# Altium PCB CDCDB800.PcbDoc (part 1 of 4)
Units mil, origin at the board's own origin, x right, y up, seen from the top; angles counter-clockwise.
Board outline 4100 x 4100 mil, 4 copper layers (Layer 1 - Top Layer, Layer 2 - GND, Layer 3 - PWR, Layer 4 - Bottom Layer), stack 61.2 mil thick; 245 components, 143 nets, 740 pads, 720 vias.
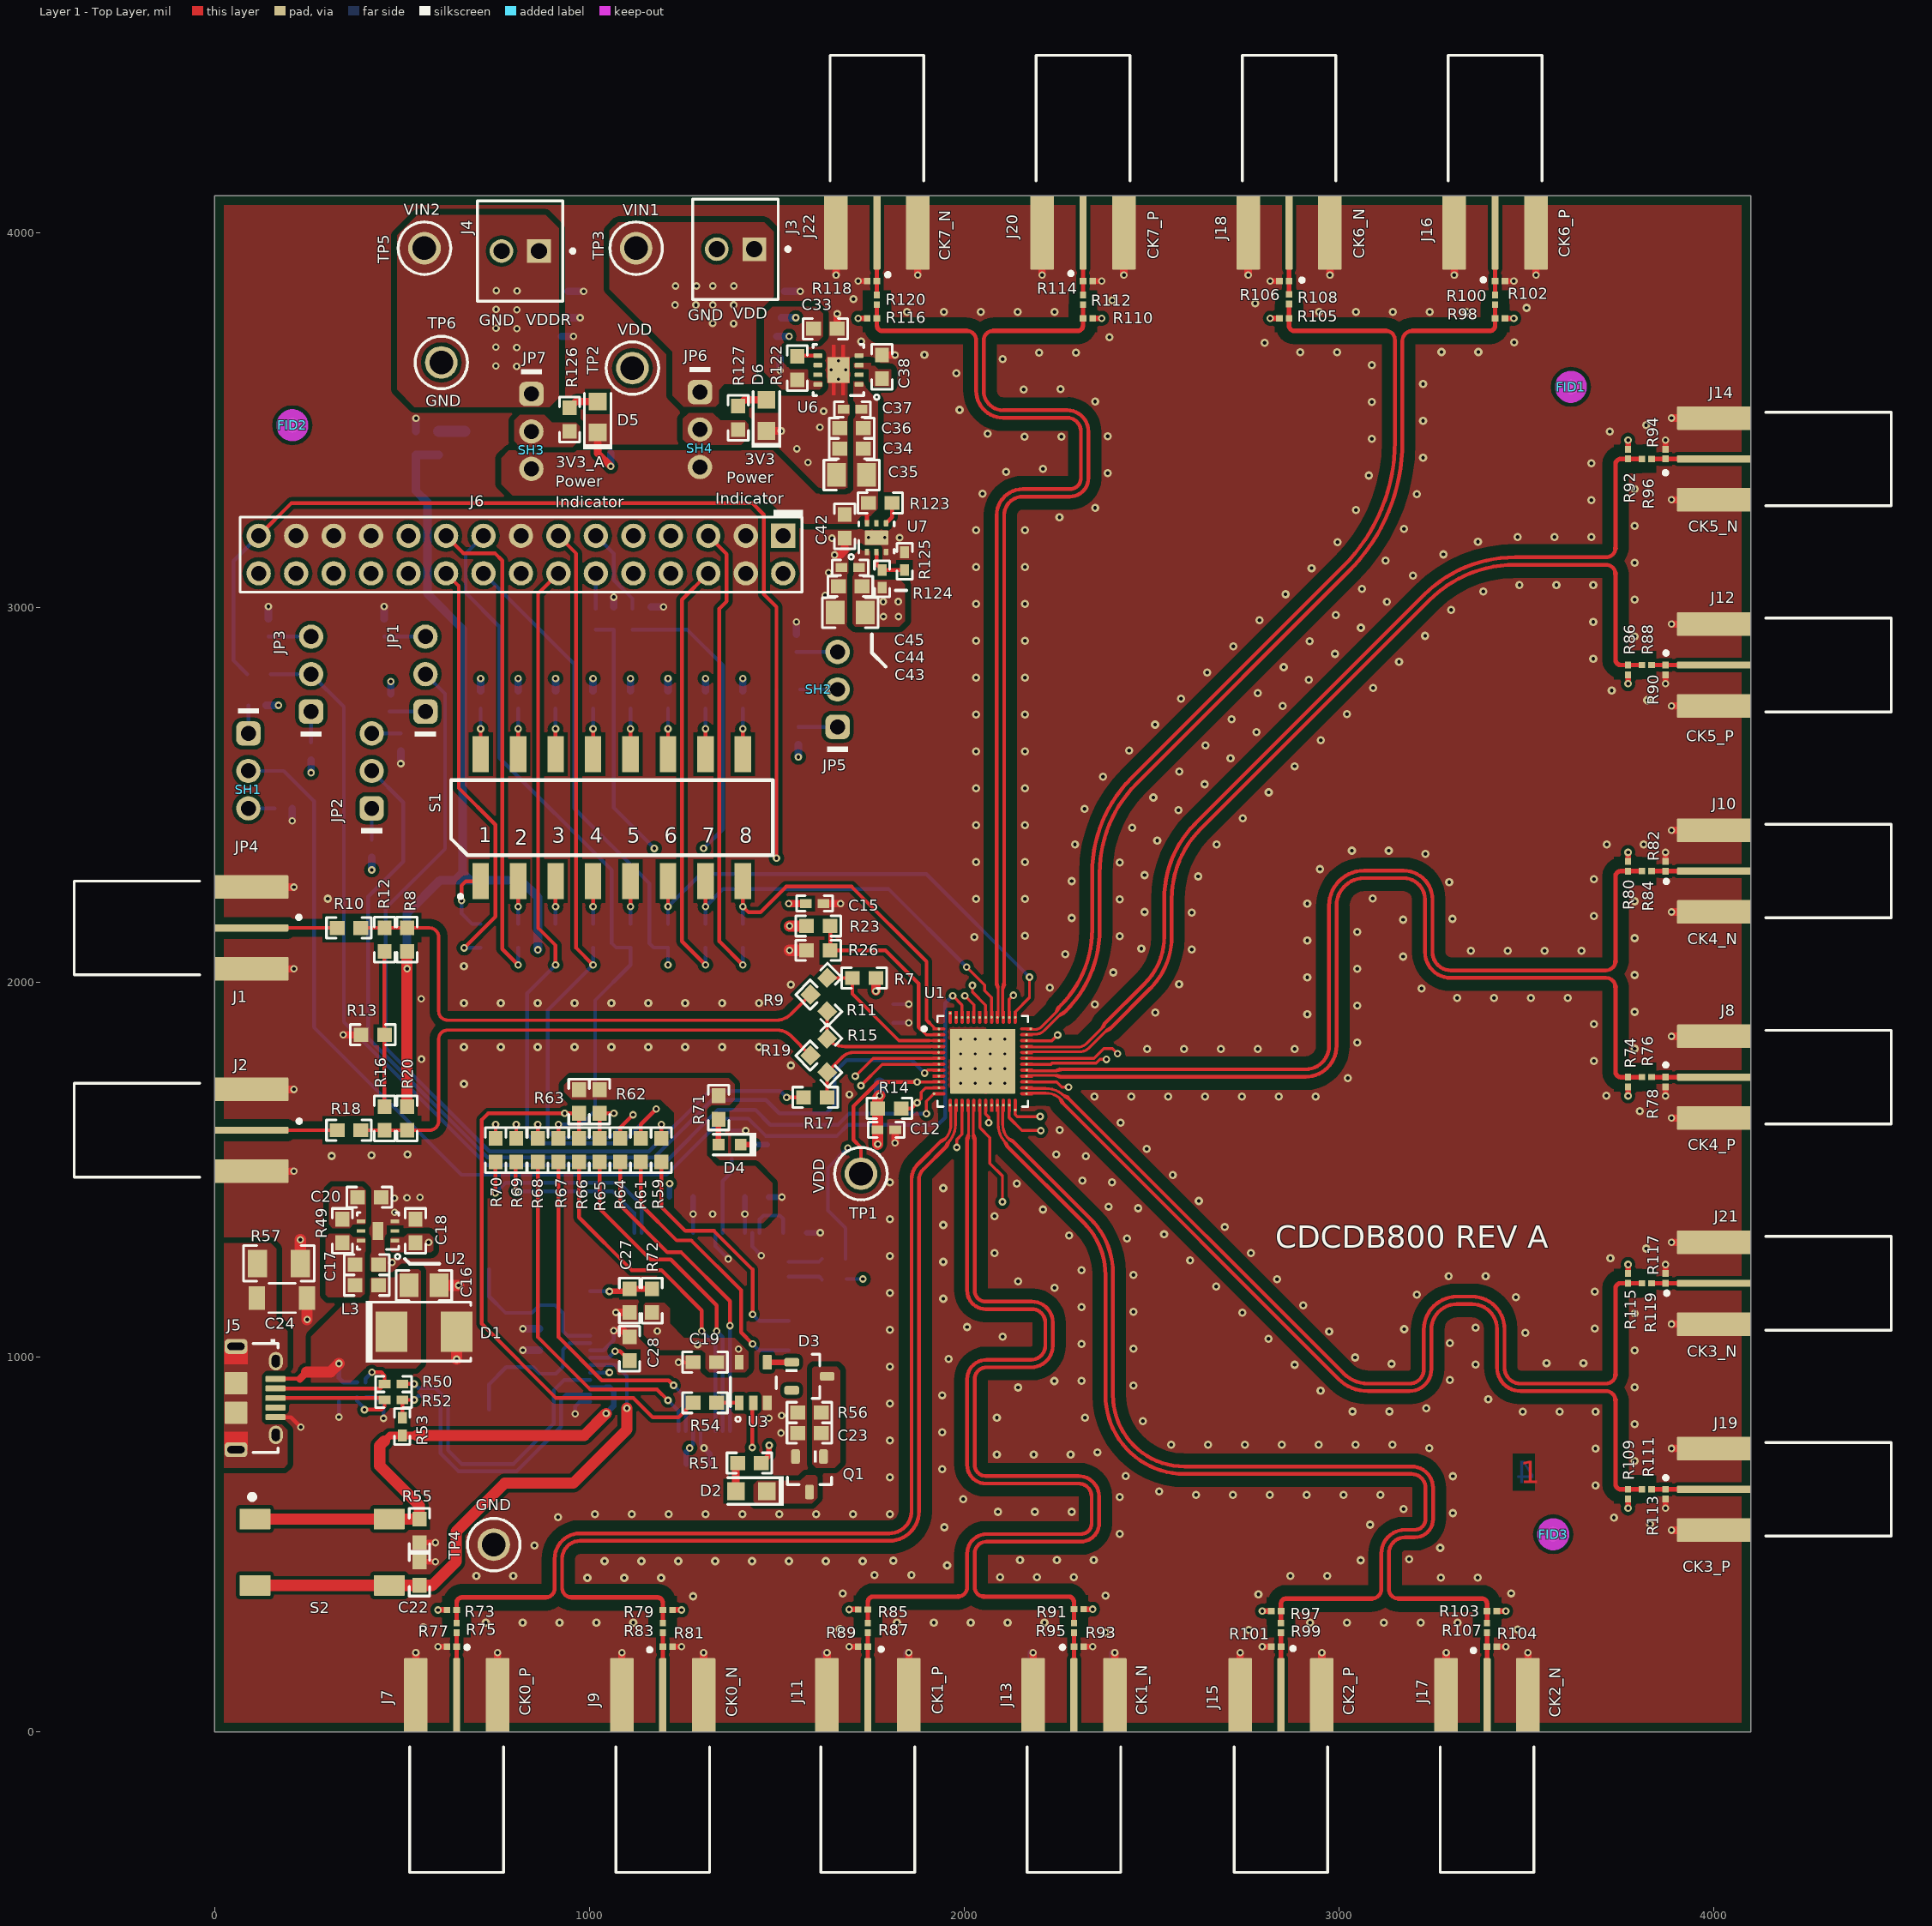
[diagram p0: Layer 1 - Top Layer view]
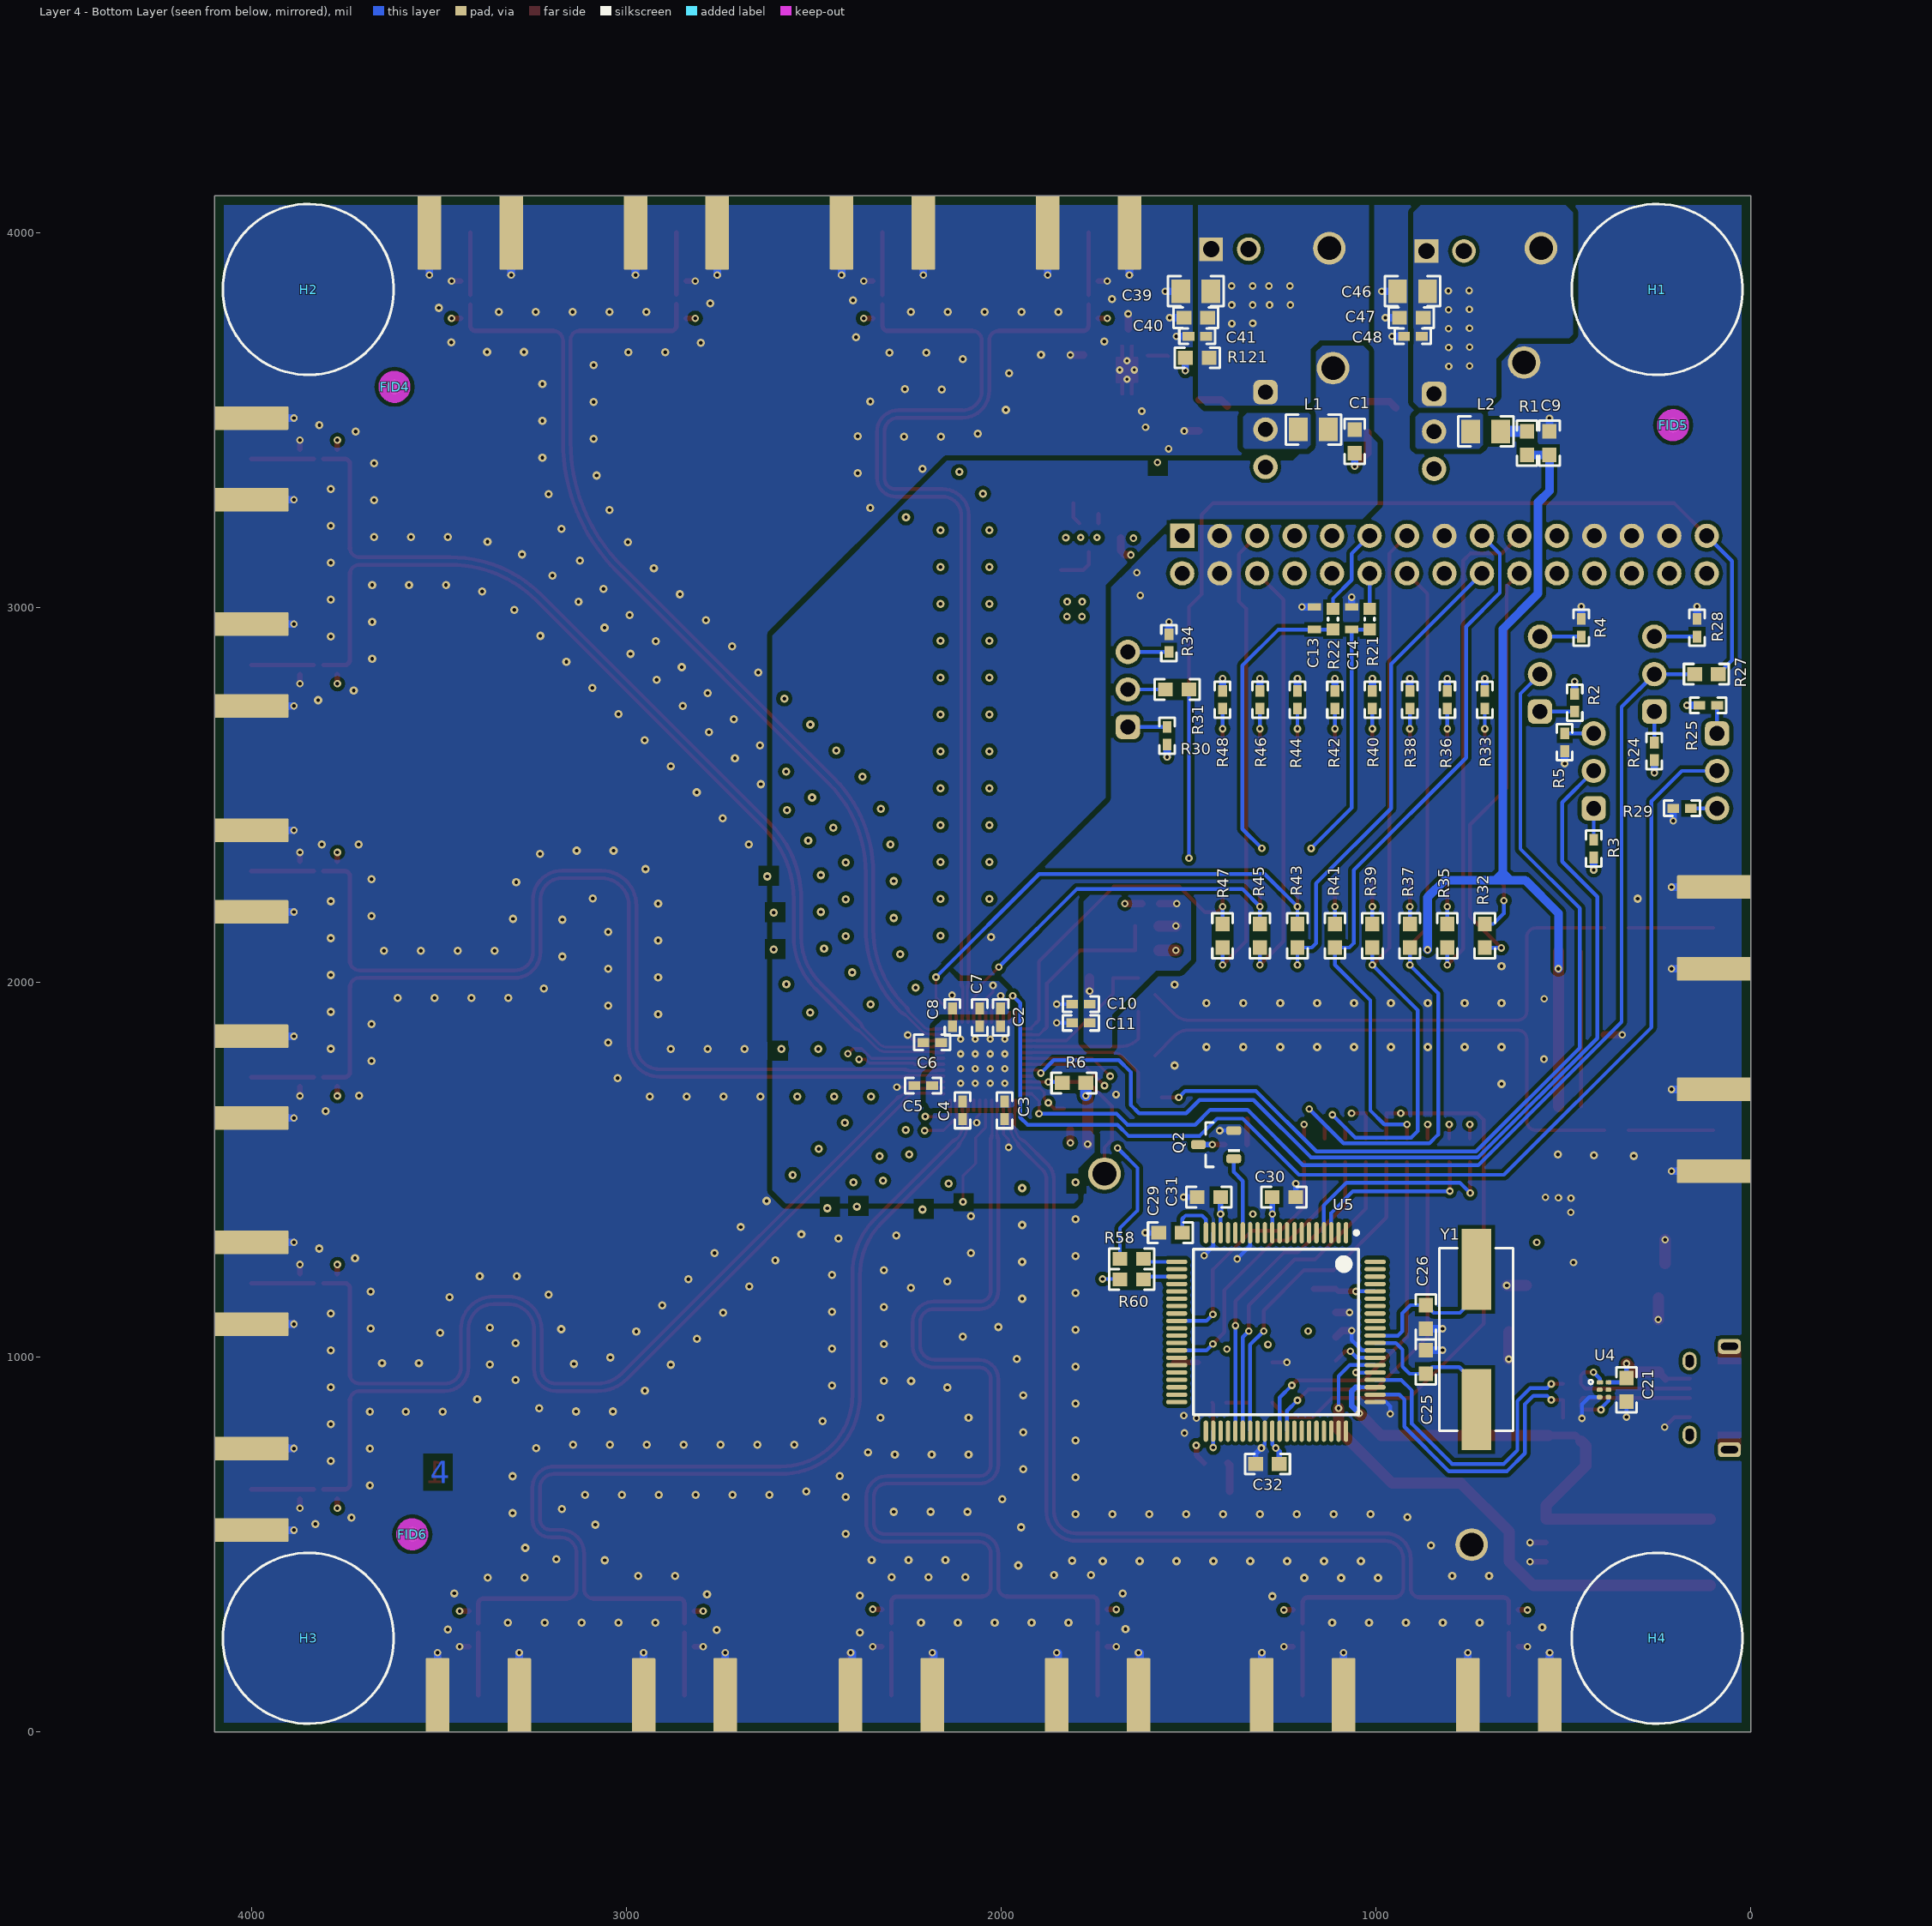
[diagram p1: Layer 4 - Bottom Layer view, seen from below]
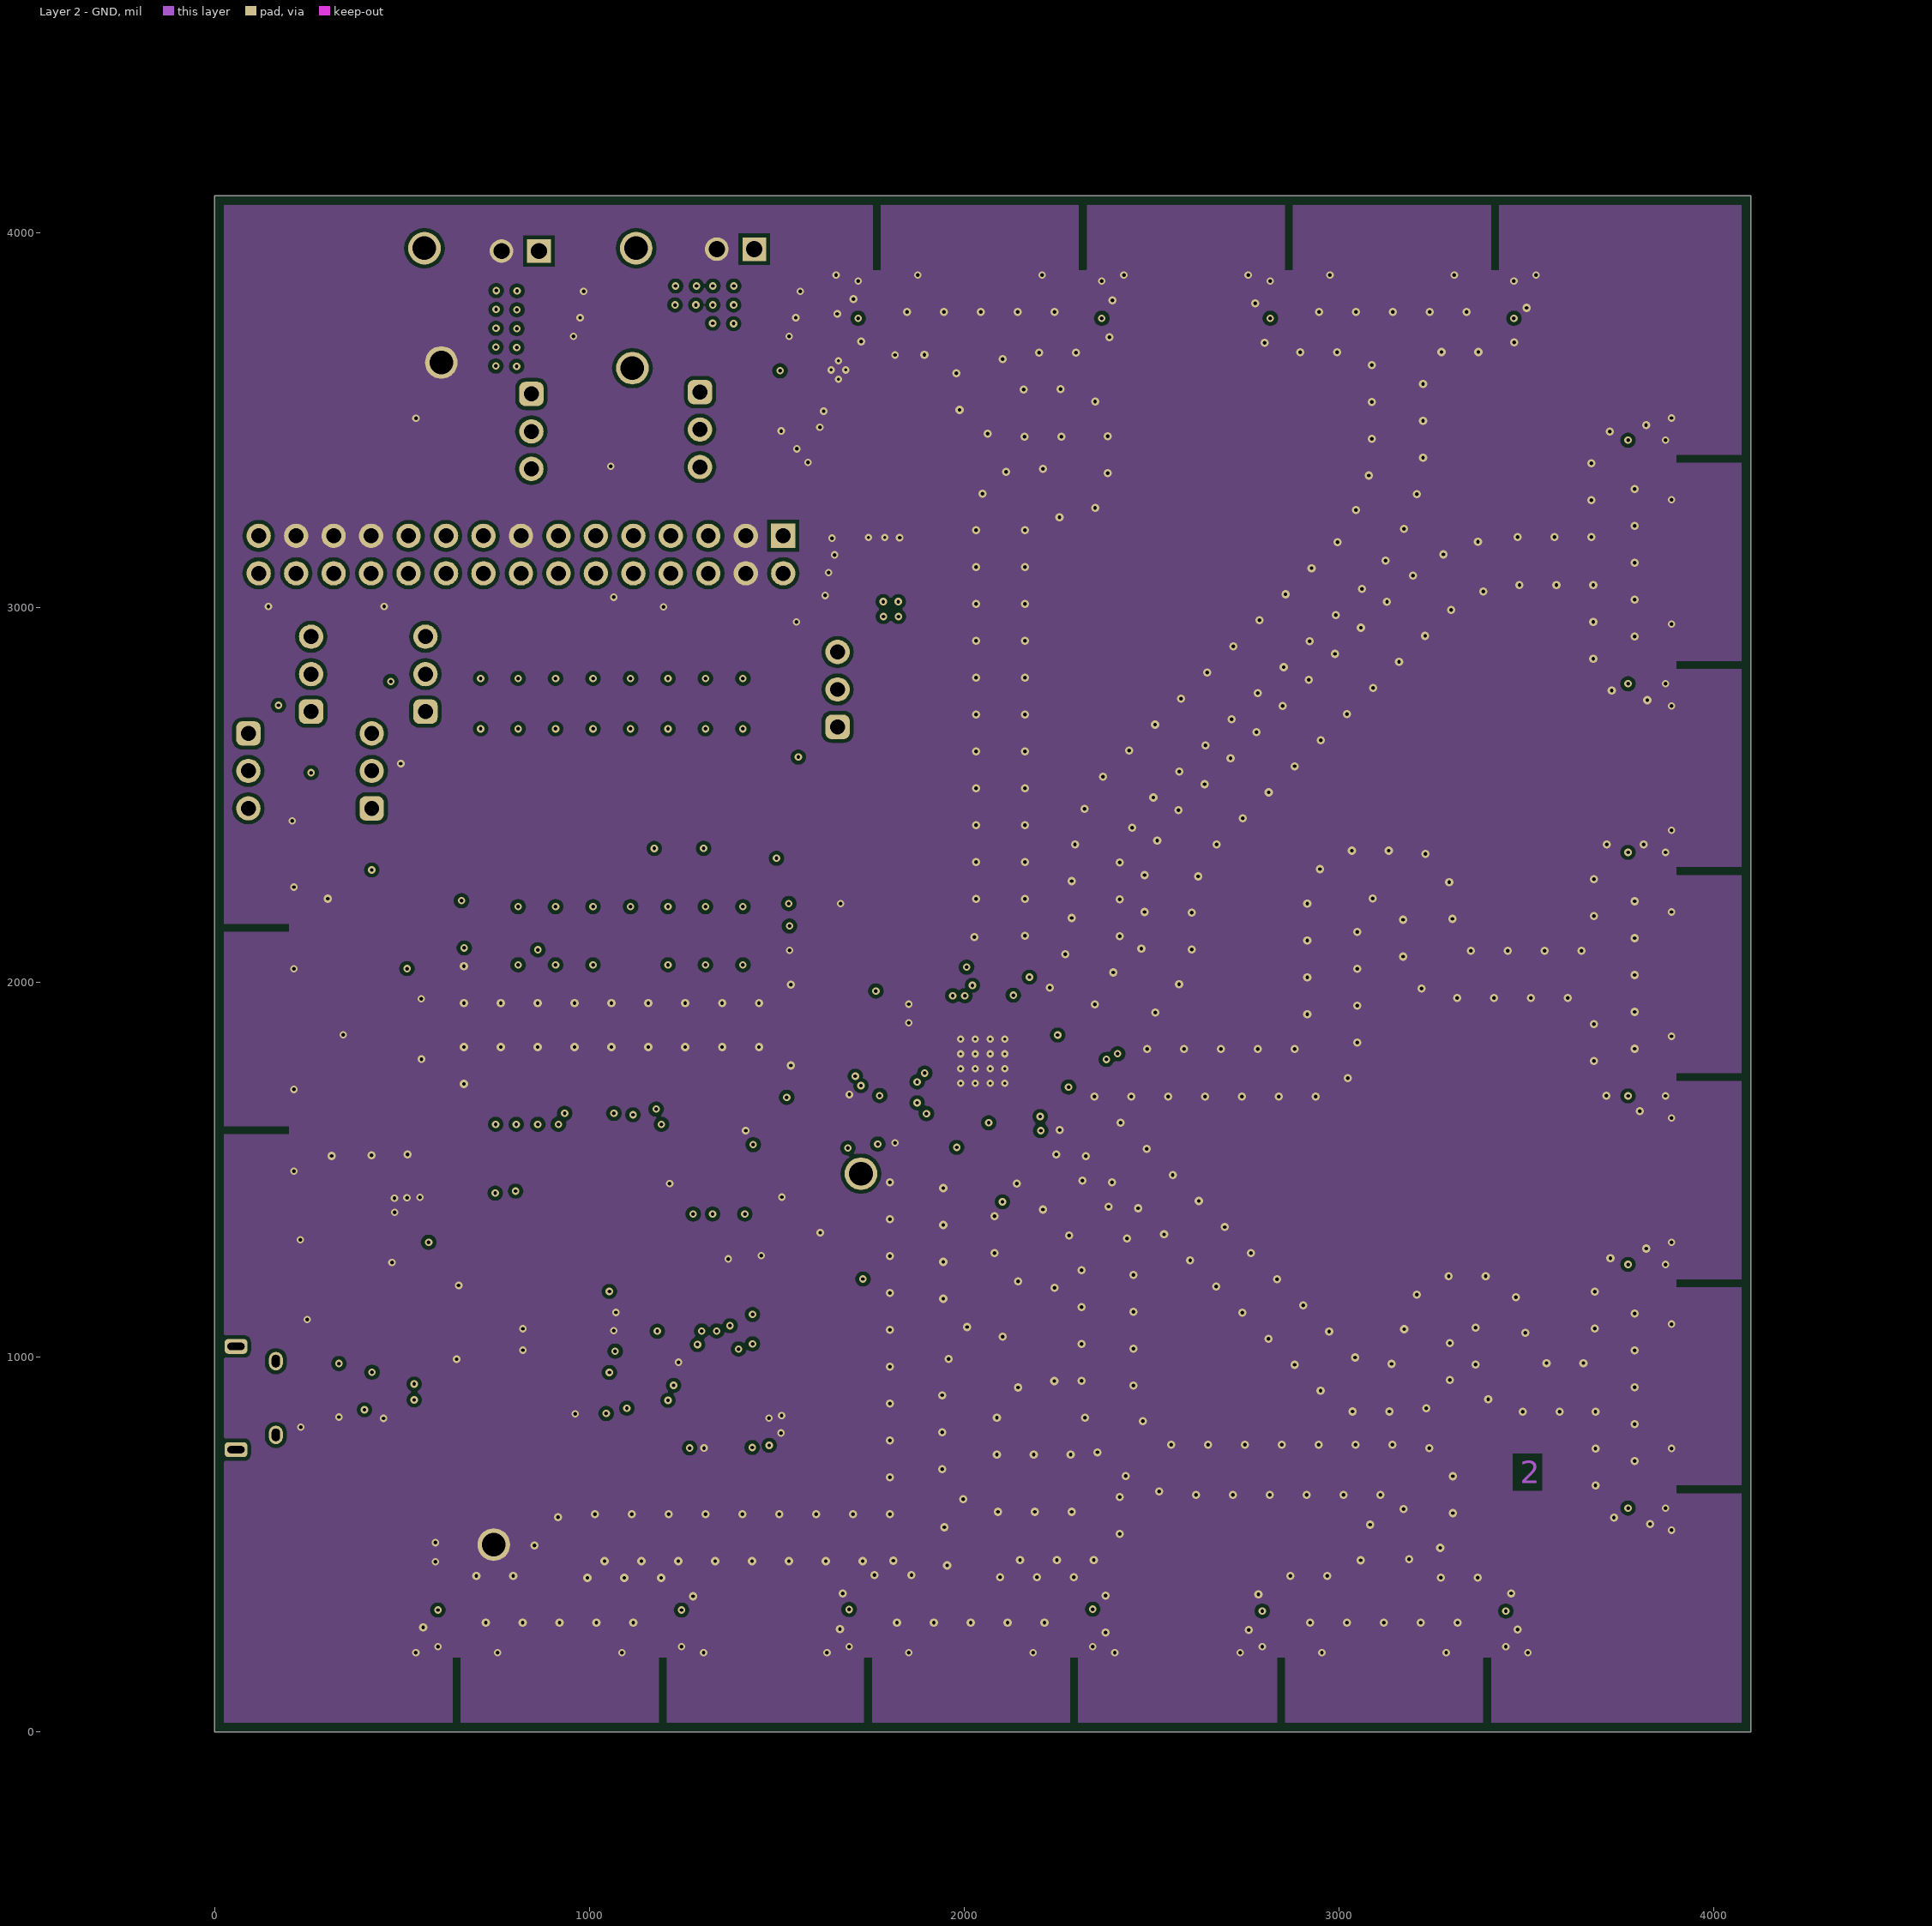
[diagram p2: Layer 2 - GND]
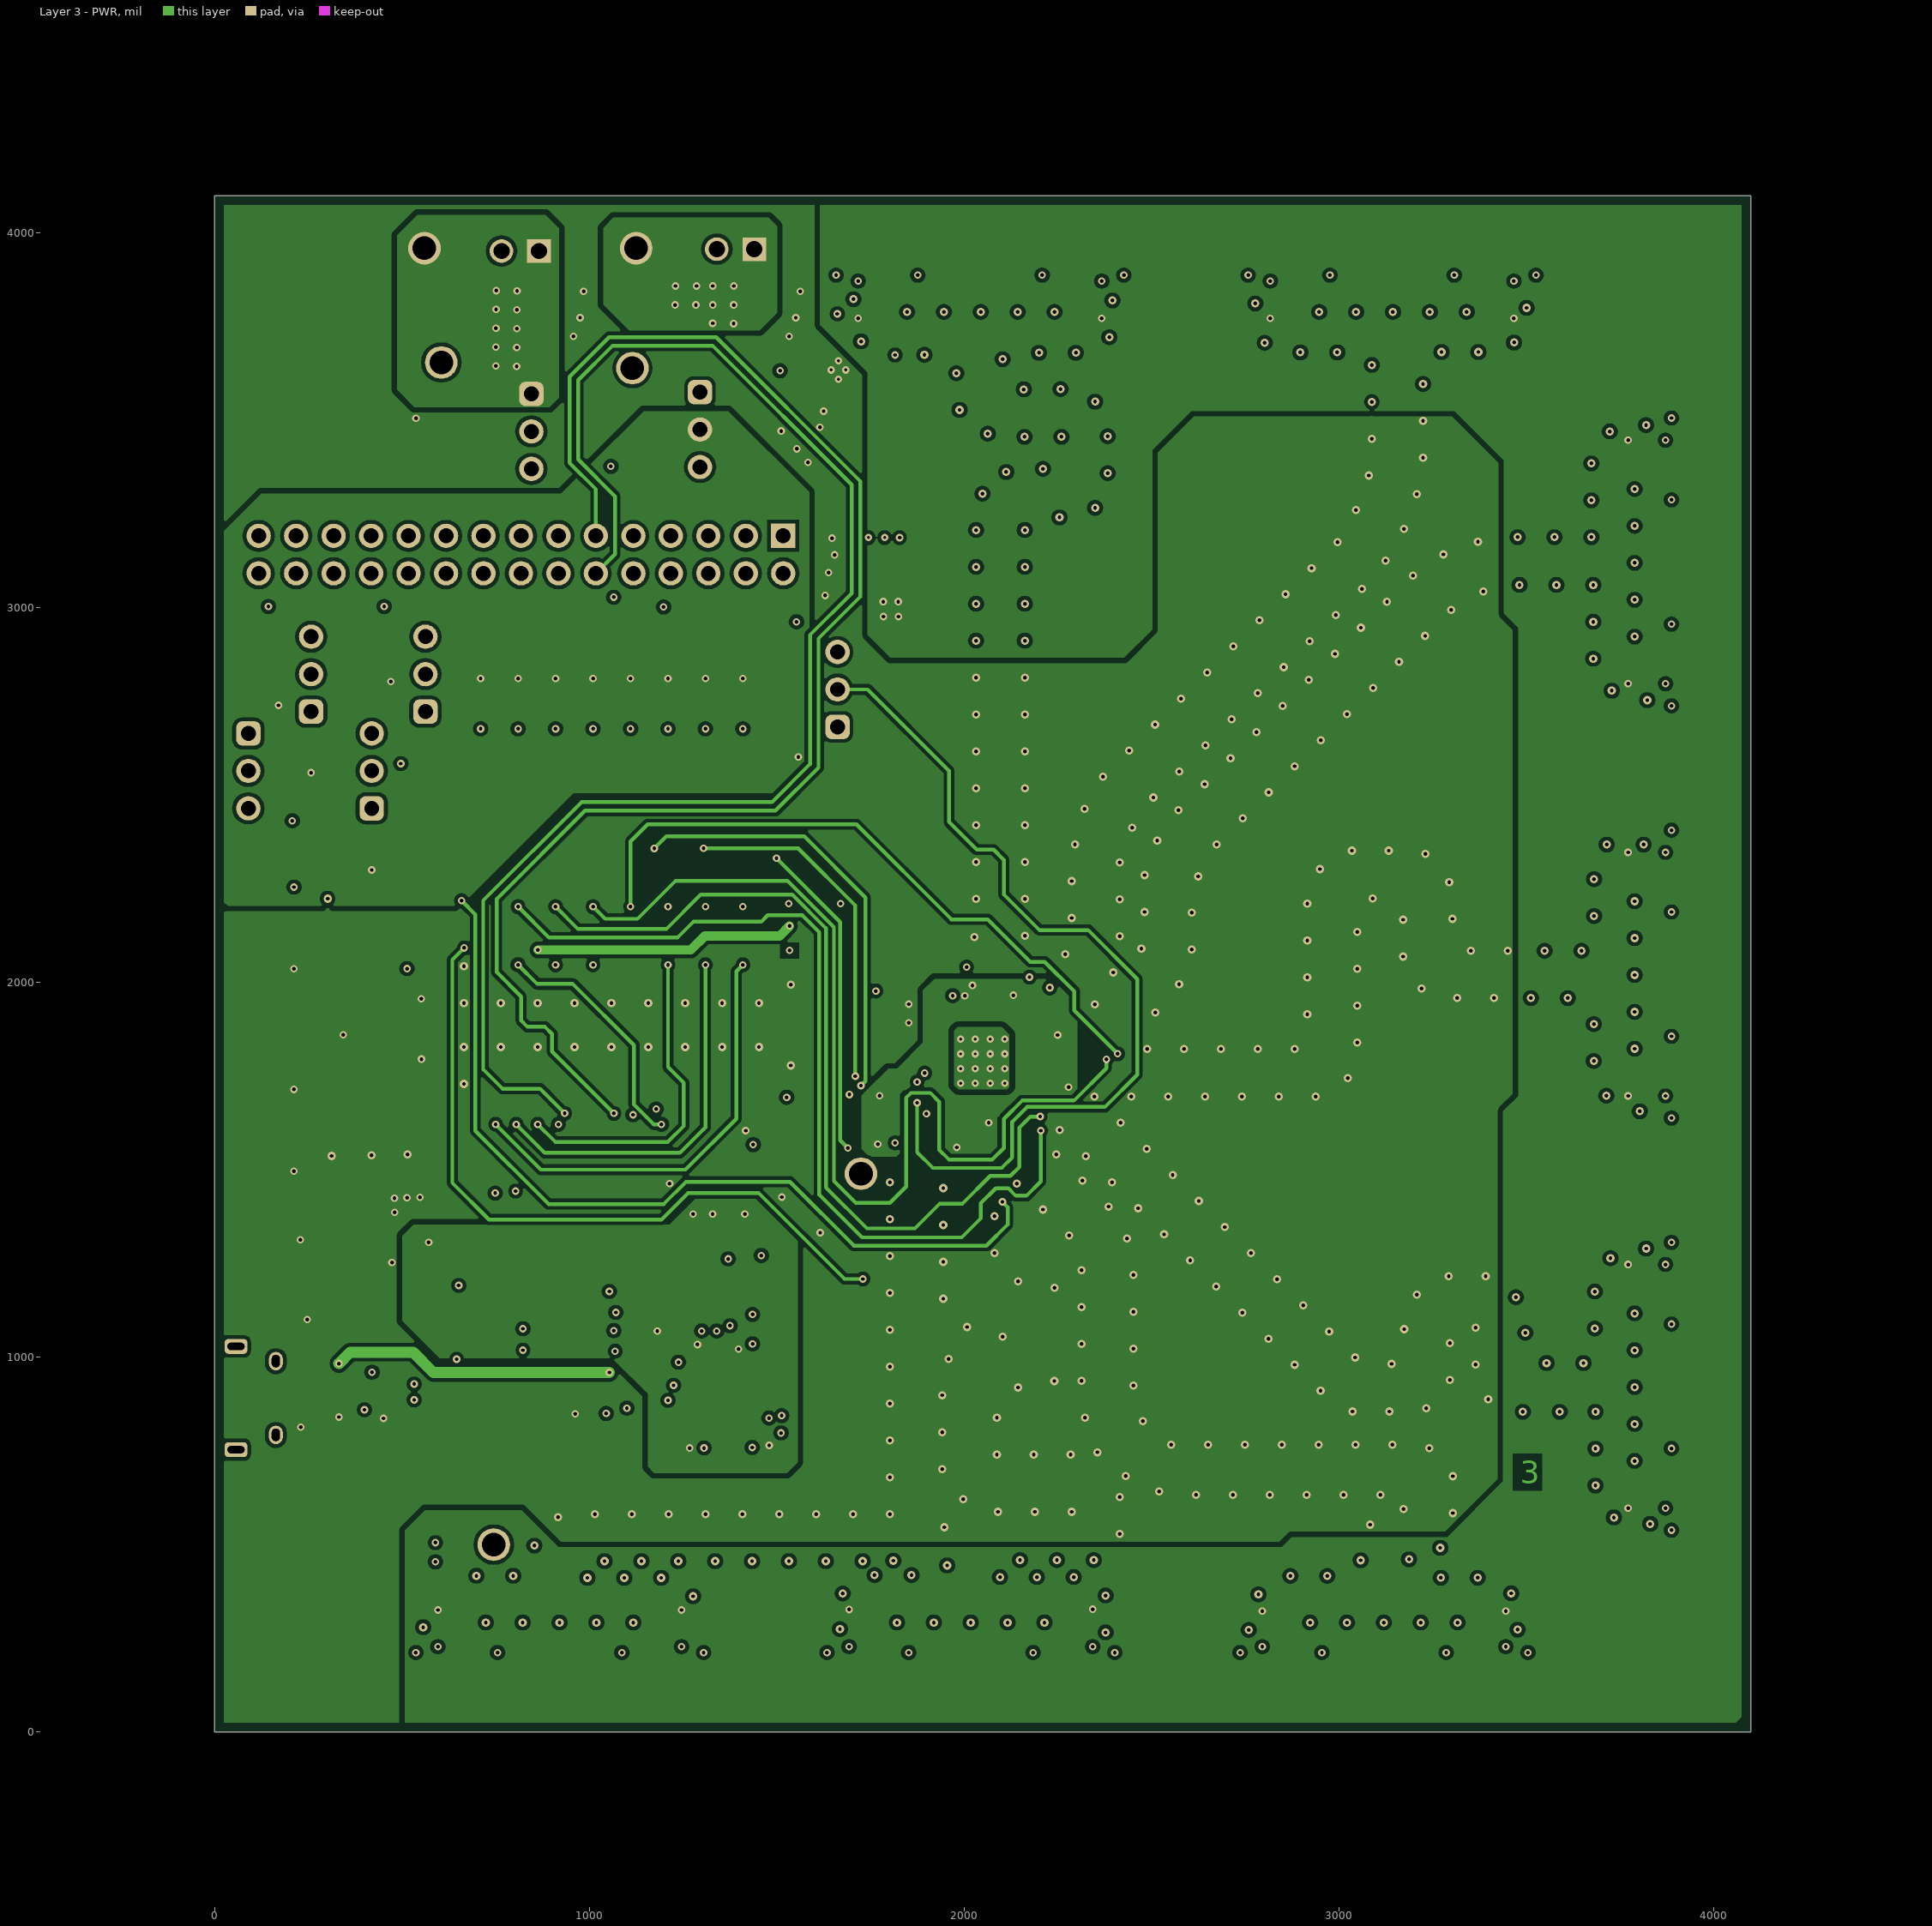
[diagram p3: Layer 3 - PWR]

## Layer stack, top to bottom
Top Solder: solder mask 0.4, Solder Resist, Dk 3.5
Layer 1 - Top Layer: signal copper 2.1
Dielectric 1: prepreg 5.5, FR-4 High Tg, Dk 4.2
Layer 2 - GND: signal copper 1.4
Dielectric 2: core 43.2, FR-4 High Tg, Dk 4.2
Layer 3 - PWR: signal copper 1.4
Dielectric 3: prepreg 5.5, FR-4 High Tg, Dk 4.2
Layer 4 - Bottom Layer: signal copper 2.1
Bottom Solder: solder mask 0.4, Solder Resist, Dk 3.5

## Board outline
0,0 4100,0 4100,4100 0,4100

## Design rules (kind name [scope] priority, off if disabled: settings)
AcuteAngle [All] p1: minimum=4.50000000000000E+0001 checktracksonly=FALSE
AssemblyTestPointUsage [All] p1: valid=2
BoardOutlineClearance BoardOutlineClearance_MountingHoles [OnCopper and InComponentClass('Mounting Holes')] p1: gap=40 ignorepadtopadclearanceinfootprint=FALSE
BoardOutlineClearance BoardOutlineClearance_Poly [OnCopper and IsPoly] p2: gap=25 ignorepadtopadclearanceinfootprint=FALSE
BoardOutlineClearance [OnCopper and Not InComponentClass('Logo') and not InComponentClass('FiducialMark') and not InRegion(1000,500,4000,800) and not InPoly] p3: gap=0 ignorepadtopadclearanceinfootprint=FALSE
Clearance Clearance_keepout [HasFootprint('Fiducial10-20') and IsPad vs HasFootprint('Fiducial10-20') and Isarc] p1: gap=0 ignorepadtopadclearanceinfootprint=FALSE
Clearance Clearance_85ohms [InPolygon vs InNetClass('85ohms')] p2: gap=30 ignorepadtopadclearanceinfootprint=FALSE
Clearance Clearance_50ohms [InPolygon vs InNetClass('50ohms')] p3: gap=20 ignorepadtopadclearanceinfootprint=FALSE
Clearance Clearance_Poly_POLY [InPolygon vs InPolygon] p4: gap=15 ignorepadtopadclearanceinfootprint=FALSE
Clearance Clearance_Poly_1 [InPolygon] p5: gap=10 ignorepadtopadclearanceinfootprint=FALSE
Clearance [All] p6: gap=5 ignorepadtopadclearanceinfootprint=FALSE
ComponentClearance ComponentClearance_1 [HasFootprint('SNT-100-BK-G')] p1: gap=0 collisioncheckmode=3 verticalgap=0 showdistances=FALSE
ComponentClearance ComponentClearance_res [InComponent('R15') vs InComponent('R19')] p2: gap=0 collisioncheckmode=3 verticalgap=0 showdistances=FALSE
ComponentClearance ComponentClearance_res_1 [InComponent('R9') vs InComponent('R11')] p3: gap=0 collisioncheckmode=3 verticalgap=0 showdistances=FALSE
ComponentClearance [All] p4: gap=10 collisioncheckmode=3 verticalgap=10 showdistances=FALSE
DiffPairsRouting [All] p1: maxlimit=17.6 minlimit=5 mostfreqgap=10 toplayer_minwidth=7.5 toplayer_maxwidth=10 toplayer_prefwidth=10 midlayer1_minwidth=7.5 midlayer1_maxwidth=10 midlayer1_prefwidth=10 midlayer2_minwidth=7.5 midlayer2_maxwidth=10 midlayer2_prefwidth=10 bottomlayer_minwidth=7.5 bottomlayer_maxwidth=10 bottomlayer_prefwidth=10 maxuncoupledlength=1000
FabricationTestPointUsage TestPointUsage [All] p1: valid=2 allowmultiple=FALSE
FabricationTestpoint Testpoint [All] p1: side=3 testpointundercomponent=TRUE minsize=40 maxsize=100 preferedsize=60 minholesize=0 maxholesize=40 preferedholesize=32 testpointgrid=1 allowsidetop=TRUE allowsidebottom=TRUE usegrid=TRUE gridtolerance=0.01
FanoutControl Fanout_LCC [IsLCC] p1: bgadir=Out bgaviamode=Centered fanoutstyle=Auto fanoutdirection=Alternating viagrid=1 // Fanout_LCC (Default Rule)
FanoutControl Fanout_BGA [IsBGA] p2: bgadir=Out bgaviamode=Centered fanoutstyle=Auto fanoutdirection=Alternating viagrid=1 // Fanout_BGA (Default Rule)
FanoutControl Fanout_Default [All] p4: bgadir=Out bgaviamode=Centered fanoutstyle=Auto fanoutdirection=Alternating viagrid=1 // Fanout_Default (Default Rule)
FanoutControl Fanout_Small [(CompPinCount < 5)] p5: bgadir=Out bgaviamode=Centered fanoutstyle=Auto fanoutdirection=OutThenIn viagrid=1 // Fanout_Small (Default Rule)
HoleSize [All] p1: absolutevalues=TRUE maxlimit=251 minlimit=6 maxpercent=80.000 minpercent=20.000
MinimumAnnularRing MinimumAnnularRing_ThermalPadVias [IsVia and InAnyComponent] p1: minimumring=5.91
MinimumAnnularRing [All] p2: minimumring=3
MinimumSolderMaskSliver MinimumSolderMaskSliver_Logo [InComponentClass('Logo') vs InComponentClass('Logo')] p1: minsoldermaskwidth=0.7
MinimumSolderMaskSliver [All] p2: minsoldermaskwidth=3
PlaneConnect [All] p1: planeconnectstyle=Relief reliefexpansion=10 reliefentries=4 reliefconductorwidth=10 reliefairgap=10
PolygonConnect PolygonConnect_1 [InNet('USB_GND') vs (InComponent('R46') OR InComponent('C19'))] p1: connectstyle=Relief reliefconductorwidth=10 reliefentries=4 polygonreliefangle="90 Angle" airgapwidth=10
PolygonConnect [All] p2: connectstyle=Direct reliefconductorwidth=10 reliefentries=4 polygonreliefangle="90 Angle" airgapwidth=10
RoutingVias ThermalPadVias [IsVia and InAnyComponent] p1: holewidth=7.87 width=19.68 viastyle="Through Hole" minholewidth=7.87 minwidth=19.68 maxholewidth=12.99 maxwidth=23.62
RoutingVias [All] p2: holewidth=16 width=34 viastyle="Through Hole" minholewidth=6 minwidth=12 maxholewidth=40 maxwidth=65
SilkToBoardRegionClearance [Not ((IsComment or IsDesignator) And (Hide <> 'False')) and not InRegion(1000,500,4000,800)] p1:
SilkToSilkClearance SilkToSilkClearance_Pb-FreeLogo [(HasFootprint('Pb-Free_Overlay_Medium') OR HasFootprint('Pb-Free_Overlay_Small')) vs (HasFootprint('Pb-Free_Overlay_Medium') OR HasFootprint('Pb-Free_Overlay_Small'))] p1: silktosilkclearance=0
SilkToSilkClearance [All] p2: silktosilkclearance=4
SilkToSolderMaskClearance SilkToComponentPadClearance [(IsPad or IsFill or IsRegion) and InAnycomponent] p1: minsilkscreentomaskgap=0 clearancetoexposedcopper=TRUE
SilkToSolderMaskClearance "Silk to Solder Mask Opening" [All] p2: minsilkscreentomaskgap=0 clearancetoexposedcopper=FALSE
SolderMaskExpansion SolderMaskExpansion_NPTH [IsThruPin and (PadIsPlated = 'FALSE')] p1: expansion=5 soldermaskfromhole=TRUE
SolderMaskExpansion SolderMaskExpansion_PTH [IsThruPin] p2: expansion=2.5
SolderMaskExpansion [All] p3: expansion=0
Width [All] p1: maxlimit=100 minlimit=5 preferedwidth=10 checkconnectedcopper=TRUE
15 further rules are at their usual default settings.

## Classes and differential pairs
component class Shunt: SH1 SH2 SH3 SH4
net class 50ohms: CLKIN_N CLKIN_N1 CLKIN_N2 CLKIN_P CLKIN_SMA_N CLKIN_SMA_P
net class 85ohms: CK0_N CK0_P CK1_N CK1_P CK2_N CK2_P CK3_N CK3_P CK4_N CK4_P CK5_N CK5_P CK6_N CK6_P CK7_N CK7_P
component class HSDC109_Power: C33 C34 C35 C36 C37 C38 C39 C40 C41 C42 C43 C44 C45 C46 C47 C48 D5 D6 J3 J4 JP6 JP7 R121 R122 R123 R124 R125 R126 R127 TP3 TP4 TP5 TP6 U6 U7
component class HSDC109_Output: J7 J8 J9 J10 J11 J12 J13 J14 J15 J16 J17 J18 J19 J20 J21 J22 R73 R74 R75 R76 R77 R78 R79 R80 R81 R82 R83 R84 R85 R86 R87 R88 R89 R90 R91 R92 R93 R94 R95 R96 R97 R98 R99 R100 R101 R102 R103 R104 R105 R106 R107 R108 R109 R110 R111 R112 R113 R114 R115 R116 R117 R118 R119 R120
component class HSDC109_Main: C1 C2 C3 C4 C5 C6 C7 C8 C9 C10 C11 C12 C13 C14 C15 J1 J2 JP1 JP2 JP3 JP4 JP5 JP12 L1 L2 R1 R2 R3 R4 R5 R6 R7 R8 R9 R10 R11 R12 R13 R14 R15 R16 R17 R18 R19 R20 R21 R22 R23 R24 R25 R26 R27 R28 R29 R30 R31 R32 R33 R34 R35 R36 R37 R38 R39 R40 R41 R42 R43 R44 R45 R46 R47 R48 S1 TP1 TP2 U1
component class Header: J6 JP1 JP2 JP3 JP4 JP5 JP6 JP7 JP12
component class HSDC109_Hardware: !PCB FID1 FID2 FID3 FID4 FID5 FID6 H1 H2 H3 H4 SH1 SH2 SH3 SH4
component class HSDC109_Control: C16 C17 C18 C19 C20 C21 C22 C23 C24 C25 C26 C27 C28 C29 C30 C31 C32 D1 D2 D3 D4 J5 J6 L3 Q1 Q2 R49 R50 R51 R52 R53 R54 R55 R56 R57 R58 R59 R60 R61 R62 R63 R64 R65 R66 R67 R68 R69 R70 R71 R72 S2 U2 U3 U4 U5 Y1
component class FiducialMark: FID1 FID2 FID3 FID4 FID5 FID6
differential pair USB_D: +USB_D_P -USB_D_N
differential pair D: +D_P -D_N
differential pair CLKIN: +CLKIN_P -CLKIN_N
differential pair CK7: +CK7_P -CK7_N
differential pair CK7_SMA: +CK7_SMA_P -CK7_SMA_N
differential pair CK6: +CK6_P -CK6_N
differential pair CK6_SMA: +CK6_SMA_P -CK6_SMA_N
differential pair CK5: +CK5_P -CK5_N
differential pair CK5_SMA: +CK5_SMA_P -CK5_SMA_N
differential pair CK4: +CK4_P -CK4_N
differential pair CK4_SMA: +CK4_SMA_P -CK4_SMA_N
differential pair CK3: +CK3_P -CK3_N
differential pair CK3_SMA: +CK3_SMA_P -CK3_SMA_N
differential pair CK2: +CK2_P -CK2_N
differential pair CK2_SMA: +CK2_SMA_P -CK2_SMA_N
differential pair CK1: +CK1_P -CK1_N
differential pair CK1_SMA: +CK1_SMA_P -CK1_SMA_N
differential pair CK0: +CK0_P -CK0_N
differential pair CK0_SMA: +CK0_SMA_P -CK0_SMA_N
differential pair CLKIN_SMA: +CLKIN_SMA_P -CLKIN_SMA_N

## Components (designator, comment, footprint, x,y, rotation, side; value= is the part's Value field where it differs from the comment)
C1 "GRM188C81C106MA73D" 0603 1057.4,3444.52 r270 bottom value=10uF
C2 "GRM155R71A104KA01D" 0402 2002.2,1907.13 r270 bottom value=0.1uF
C3 "GRM155R71A104KA01D" 0402 1991.7,1659.2 r90 bottom value=0.1uF
C4 "GRM155R71A104KA01D" 0402 2103.7,1659.2 r90 bottom value=0.1uF
C5 "GRM155R71A104KA01D" 0402 2208.9,1725.1 r180 bottom value=0.1uF
C6 "GRM155R71A104KA01D" 0402 2184.68,1840.3 r180 bottom value=0.1uF
C7 "GRM155R71A104KA01D" 0402 2057.87,1907.13 r270 bottom value=0.1uF
C8 "GRM155R71A104KA01D" 0402 2130.8,1907.13 r270 bottom value=0.1uF
C9 "GRM188C81C106MA73D" 0603 537.4,3439.52 r90 bottom value=10uF
C10 "GRM155R71A104KA01D" 0402 1787.87,1942.53 r0 bottom value=0.1uF
C11 "GRM155R71A104KA01D" 0402 1787.87,1892.53 r0 bottom value=0.1uF
C12 "GRM155R71A104KA01D" 0402 1792.87,1607.13 r0 top locked value=0.1uF
C13 "06031A330JAT2A" 0603S 1165,2972.44 r90 bottom value=33pF
C14 "06031A330JAT2A" 0603S 1065,2972.44 r90 bottom value=33pF
C15 "GRM155R71A104KA01D" 0402 1601.5,2211.02 r0 top locked value=0.1uF
C16 "LMK212BJ226MG-T" 0805_HV 558.78,1192.11 r0 top locked value=22uF
C17 "C1608X5R1A106M080AC" 0603 405.95,1247.11 r0 top locked value=10uF
C18 "C1608X5R1A106M080AC" 0603 535.95,1337.11 r90 top locked value=10uF
C19 "C0603C104J4RACTU" 0603 1308.5,986.73 r180 top locked value=0.1uF
C20 "C0603C104J4RACTU" 0603 412.95,1427.11 r0 top locked value=0.1uF
C21 "C0603C104J4RACTU" 0603 331.78,913.29 r90 bottom value=0.1uF
C22 "06035A221FAT2A" 0603 546.78,422.66 r90 top locked value=220pF
C23 "C0603C103J5RACTU" 0603 1587.6,797.6 r180 top locked value=0.01uF
C24 "C3216X7R1H475K160AE" 1206_190 180.02,1158.44 r180 top value=4.7uF
C25 "GRM1885C2A300JA01D" 0603 867.4,987.6 r90 bottom value=30pF
C26 "GRM1885C2A300JA01D" 0603 867.4,1107.6 r270 bottom value=30pF
C27 "C0603C222K5RACTU" 0603 1107.4,1151.1 r270 top locked value=2200pF
C28 "06035A221FAT2A" 0603 1107.4,1022.6 r90 top locked value=220pF
C29 "GRM188R71A474KA61D" 0603 1548.9,1332.36 r0 bottom value=0.47uF
C30 "C0603C104J4RACTU" 0603 1245.91,1427.6 r180 bottom value=0.1uF
C31 "C0603C104J4RACTU" 0603 1446.54,1427.44 r0 bottom value=0.1uF
C32 "C0603C104J4RACTU" 0603 1290,715 r0 bottom value=0.1uF
C33 "CGA3E1X7R1V105K080AC" 0603 1630,3745 r0 top locked value=1uF
C34 "GRM188Z71A106MA73D" 0603 1700,3425 r180 top locked value=10uF
C35 "LMK212BJ226MG-T" 0805_HV 1700,3355 r180 top locked value=22uF
C36 "GRM188C81C106MA73D" 0603 1700,3480 r180 top locked value=10uF
C37 "GRM155R71A104KA01D" 0402 1702.5,3530 r180 top locked value=0.1uF
C38 "0603ZC103KAT2A" 0603 1781,3643.5 r90 top locked value=0.01uF
C39 "LMK212BJ226MG-T" 0805_HV 1481.26,3845.12 r0 bottom value=22uF
C40 "GRM188C81C106MA73D" 0603 1481.26,3774.41 r0 bottom value=10uF
C41 "GRM155R71A104KA01D" 0402 1477.26,3724.91 r0 bottom value=0.1uF
C42 "CGA3E1X7R1V105K080AC" 0603 1681.5,3217.61 r270 top locked value=1uF
C43 "LMK212BJ226MG-T" 0805_HV 1696.5,2987.61 r180 top locked value=22uF
C44 "GRM188C81C106MA73D" 0603 1696.5,3057.61 r180 top locked value=10uF
C45 "GRM155R71A104KA01D" 0402 1696.5,3107.61 r180 top locked value=0.1uF
C46 "LMK212BJ226MG-T" 0805_HV 902.88,3845.12 r0 bottom value=22uF
C47 "GRM188C81C106MA73D" 0603 905.88,3774.41 r0 bottom value=10uF
C48 "GRM155R71A104KA01D" 0402 901.88,3724.91 r0 bottom value=0.1uF
D1 "1SMB5922BT3G" SMB 558.78,1068.29 r0 top locked value=7.5V
D2 "LTST-C170KRKT" LED_LTST-C170_Red 1432.4,642.6 r0 top locked value=Red
D3 "BAT54-7-F" SOT-23 1587.6,949.33 r0 top locked value=30V
D4 "LTST-C190GKT" LED_LTST-C190 1374.53,1567.6 r0 top locked value=Green
D5 "LTST-C170KRKT" LED_LTST-C170_Red 1022.4,3509.35 r270 top locked value=Red
D6 "LTST-C170KRKT" LED_LTST-C170_Red 1472.4,3513.9 r270 top locked value=Red
FID1 "Fiducial" Fiducial10-20 3620,3590 r0 top locked
FID2 "Fiducial" Fiducial10-20 207.6,3487.6 r0 top locked
FID3 "Fiducial" Fiducial10-20 3572.6,527.6 r0 top locked
FID4 "Fiducial" Fiducial10-20 3620,3590 r180 bottom
FID5 "Fiducial" Fiducial10-20 207.6,3487.6 r180 bottom
FID6 "Fiducial" Fiducial10-20 3572.6,527.6 r180 bottom
H1 "SJ-5303 (CLEAR)" Bumpon_SJ5003Transparent 250,3850 r180 bottom
H2 "SJ-5303 (CLEAR)" Bumpon_SJ5003Transparent 3850,3850 r0 bottom
H3 "SJ-5303 (CLEAR)" Bumpon_SJ5003Transparent 3850,250 r180 bottom
H4 "SJ-5303 (CLEAR)" Bumpon_SJ5003Transparent 250,250 r180 bottom
J1 "CON-SMA-EDGE-S" FP-SMA-EDGE-S-CUSTOM -187.4,2145.85 r90 top
J2 "CON-SMA-EDGE-S" FP-SMA-EDGE-S-CUSTOM -187.4,1605.85 r90 top
J3 "282834-2" TEC_282834-2 1390.2,3957.51 r180 top locked
J4 "282834-2" TEC_282834-2 815.58,3952.51 r180 top locked
J5 "10118194-0001LF" FCI_10118194-0001LF 0,891.22 r270 top locked
J6 "MTSW-115-22-G-D-315" SAMTEC_MTSW-115-22-G-D-315 817.6,3142.4 r180 top locked
J7 "CON-SMA-EDGE-S" FP-SMA-EDGE-S-CUSTOM 646.04,-187.4 r180 top locked
J8 "CON-SMA-EDGE-S" FP-SMA-EDGE-S-CUSTOM 4287.4,1747.6 r270 top locked
J9 "CON-SMA-EDGE-S" FP-SMA-EDGE-S-CUSTOM 1196.04,-187.4 r180 top locked
J10 "CON-SMA-EDGE-S" FP-SMA-EDGE-S-CUSTOM 4287.4,2297.6 r270 top locked
J11 "CON-SMA-EDGE-S" FP-SMA-EDGE-S-CUSTOM 1743.5,-187.4 r180 top locked
J12 "CON-SMA-EDGE-S" FP-SMA-EDGE-S-CUSTOM 4287.4,2847.6 r270 top locked
J13 "CON-SMA-EDGE-S" FP-SMA-EDGE-S-CUSTOM 2293.5,-187.4 r180 top locked
J14 "CON-SMA-EDGE-S" FP-SMA-EDGE-S-CUSTOM 4287.4,3397.6 r270 top locked
J15 "CON-SMA-EDGE-S" FP-SMA-EDGE-S-CUSTOM 2846.04,-187.4 r180 top locked
J16 "CON-SMA-EDGE-S" FP-SMA-EDGE-S-CUSTOM 3417.6,4287.4 r0 top locked
J17 "CON-SMA-EDGE-S" FP-SMA-EDGE-S-CUSTOM 3396.04,-187.4 r180 top locked
J18 "CON-SMA-EDGE-S" FP-SMA-EDGE-S-CUSTOM 2867.6,4287.4 r0 top locked
J19 "CON-SMA-EDGE-S" FP-SMA-EDGE-S-CUSTOM 4287.4,647.6 r270 top locked
J20 "CON-SMA-EDGE-S" FP-SMA-EDGE-S-CUSTOM 2317.6,4287.4 r0 top locked
J21 "CON-SMA-EDGE-S" FP-SMA-EDGE-S-CUSTOM 4287.4,1197.6 r270 top locked
J22 "CON-SMA-EDGE-S" FP-SMA-EDGE-S-CUSTOM 1767.6,4287.4 r0 top locked
JP1 "TSW-103-07-G-S" TSW-103-07-G-S 562.6,2823.25 r90 top locked
JP2 "TSW-103-07-G-S" TSW-103-07-G-S 419.29,2565 r90 top locked
JP3 "TSW-103-07-G-S" TSW-103-07-G-S 257.6,2823.25 r90 top locked
JP4 "TSW-103-07-G-S" TSW-103-07-G-S 90,2565 r270 top locked
JP5 "TSW-103-07-G-S" TSW-103-07-G-S 1662.6,2782.4 r90 top locked
JP6 "TSW-103-07-G-S" TSW-103-07-G-S 1295.4,3476.01 r270 top locked
JP7 "TSW-103-07-G-S" TSW-103-07-G-S 845.4,3471.01 r270 top locked
L1 "742792037" 0805_HV 1167.4,3476.01 r180 bottom value="330 ohm"
L2 "742792037" 0805_HV 707.4,3471.01 r180 bottom value="330 ohm"
L3 "MPZ1608S600ATAH0" 0603 405.95,1192.11 r180 top locked value="60 ohm"
Q1 "FDV301N" SOT-23 1587.6,687.6 r270 top locked value=25V
Q2 "BSS138" SOT-23 1427.4,1567.6 r0 bottom value=50V
R1 "ERJ-3RQF2R2V" 0603 597.4,3439.52 r270 bottom value=2.20
R2 "RC0402FR-074K99L" 0402 470.1,2746.87 r90 bottom value=4.99k
R3 "RC0402FR-074K99L" 0402 419.29,2357.4 r270 bottom value=4.99k
R4 "RC0402FR-074K99L" 0402 452.6,2946.87 r270 bottom value=4.99k
R5 "RC0402FR-074K99L" 0402 496.89,2641.38 r90 bottom value=4.99k
R6 "MCT06030Z0000ZP500" 0603 1806.38,1732.13 r0 bottom value=0
R7 "RC0603JR-070RL" 0603 1733.3,2012.29 r180 top value=0
R8 "CRCW0603100RFKEA" 0603 513.5,2114.35 r90 top locked value=100
R9 "RC0603JR-070RL" 0603 1612.6,1990.02 r45 top value=0
R10 "RC0603JR-070RL" 0603 358.5,2145.85 r0 top locked value=0
R11 "RC0603JR-070RL" 0603 1612.6,1945.47 r315 top value=0
R12 "CRCW0603100RFKEA" 0603 453.5,2114.35 r270 top locked value=100
R13 "RC0603JR-070RL" 0603 422.01,1860.85 r0 top locked value=0
R14 "MCT06030Z0000ZP500" 0603 1801.38,1664.13 r180 top locked value=0
R15 "RC0603JR-070RL" 0603 1612.6,1827.52 r45 top value=0
R16 "CRCW0603100RFKEA" 0603 453.5,1637.34 r270 top locked value=100
R17 "RC0603JR-070RL" 0603 1603.38,1693.77 r0 top value=0
R18 "RC0603JR-070RL" 0603 358.5,1605.85 r0 top locked value=0
R19 "RC0603JR-070RL" 0603 1612.6,1782.97 r315 top value=0
R20 "CRCW0603100RFKEA" 0603 513.5,1637.34 r90 top locked value=100
R21 "CRCW06030000Z0EA" 0603L 1017.6,2970 r270 bottom value=0
R22 "CRCW06030000Z0EA" 0603L 1115,2970 r270 bottom value=0
R23 "MCT06030Z0000ZP500" 0603 1611.38,2151.02 r180 top locked value=0
R24 "RC0402FR-074K99L" 0402 257.6,2617.03 r270 bottom value=4.99k
R25 "RC0402FR-074K99L" 0402 113.62,2740 r0 bottom value=4.99k
R26 "MCT06030Z0000ZP500" 0603 1611.38,2086.02 r0 top locked value=0
R27 "CRCW060322R0JNEA" 0603 118.5,2823.25 r0 bottom value=22
R28 "RC0402FR-074K99L" 0402 143.5,2946.87 r90 bottom value=4.99k
R29 "RC0402FR-074K99L" 0402 183.62,2465 r0 bottom value=4.99k
R30 "RC0402FR-074K99L" 0402 1557.91,2658.78 r270 bottom value=4.99k
R31 "CRCW060322R0JNEA" 0603 1531.1,2782.4 r0 bottom value=22
R32 "CRCW060322R0JNEA" 0603 710,2125 r90 bottom value=22
R33 "RC0402FR-074K99L" 0402 710,2755 r270 bottom value=4.99k
R34 "RC0402FR-074K99L" 0402 1552.91,2906.02 r90 bottom value=4.99k
R35 "CRCW060322R0JNEA" 0603 810,2125 r90 bottom value=22
R36 "RC0402FR-074K99L" 0402 810,2755 r270 bottom value=4.99k
R37 "CRCW060322R0JNEA" 0603 910,2125 r90 bottom value=22
R38 "RC0402FR-074K99L" 0402 910,2755 r270 bottom value=4.99k
R39 "CRCW060322R0JNEA" 0603 1010,2125 r90 bottom value=22
R40 "RC0402FR-074K99L" 0402 1010,2755 r270 bottom value=4.99k
R41 "CRCW060322R0JNEA" 0603 1110,2125 r90 bottom value=22
R42 "RC0402FR-074K99L" 0402 1110,2755 r270 bottom value=4.99k
R43 "CRCW060322R0JNEA" 0603 1210,2125 r90 bottom value=22
R44 "RC0402FR-074K99L" 0402 1210,2755 r90 bottom value=4.99k
R45 "CRCW060322R0JNEA" 0603 1310,2125 r90 bottom value=22
R46 "RC0402FR-074K99L" 0402 1310,2755 r90 bottom value=4.99k
R47 "CRCW060322R0JNEA" 0603 1410,2125 r90 bottom value=22
R48 "RC0402FR-074K99L" 0402 1410,2755 r90 bottom value=4.99k
R49 "CRCW060333K0JNEA" 0603 340.95,1337.11 r270 top locked value=33k
R50 "CRCW040233R0JNED" 0402 477.3,928.7 r0 top locked value=33
R51 "CRCW0603470RJNEA" 0603 1427.4,717.6 r0 top locked value=470
R52 "CRCW040233R0JNED" 0402 477.3,886.27 r0 top locked value=33
R53 "CRCW04021K50JNED" 0402 500.92,814.85 r90 top locked value=1.5k
R54 "CRCW06030000Z0EA" 0603 1308.5,878.46 r0 top locked value=0
R55 "CRCW06031M20JNEA" 0603 546.78,536.83 r90 top locked value=1.2Meg
R56 "CRCW0603100KJNEA" 0603 1587.6,852.6 r0 top locked value=100k
R57 "RC1206FR-07110KL" 1206 171.78,1250.36 r0 top locked value=110k
R58 "CRCW06030000Z0EA" 0603 1652.4,1262.6 r180 bottom value=0
R59 "CRCW06030000Z0EA" 0603 1192.4,1552.6 r90 top locked value=0
R60 "CRCW06030000Z0EA" 0603 1652.4,1207.6 r180 bottom value=0
R61 "CRCW06030000Z0EA" 0603 1137.4,1552.6 r90 top locked value=0
R62 "RC0603JR-079K1L" 0603 1027.4,1682.6 r90 top locked value=9.1k
R63 "RC0603JR-079K1L" 0603 972.4,1682.6 r90 top locked value=9.1k
R64 "CRCW06030000Z0EA" 0603 1082.4,1552.6 r90 top locked value=0
R65 "CRCW06030000Z0EA" 0603 1027.4,1552.6 r90 top locked value=0
R66 "CRCW06030000Z0EA" 0603 972.4,1552.6 r90 top locked value=0
R67 "CRCW06030000Z0EA" 0603 917.4,1552.6 r90 top locked value=0
R68 "CRCW0603100RJNEA" 0603 862.4,1552.6 r90 top value=100
R69 "CRCW06030000Z0EA" 0603 805,1552.6 r90 top value=0
R70 "CRCW06030000Z0EA" 0603 750,1552.6 r90 top value=0
R71 "CRCW0603510RJNEA" 0603 1345,1666.5 r90 top locked value=510
R72 "CRCW060333K0JNEA" 0603 1167.4,1151.1 r270 top locked value=33k
R73 "RC0201FR-0784R5L" 0201 633.05,325.59 r180 top locked value=84.5
R74 "RC0201FR-0784R5L" 0201 3772.4,1734.61 r270 top locked value=84.5
R75 "RC0201FR-0747R5L" 0201 646.04,277.6 r270 top locked value=47.5
R76 "RC0201FR-0747R5L" 0201 3822.4,1747.6 r0 top locked value=47.5
R77 "RC0201FR-07147RL" 0201 633.05,227.6 r0 top locked value=147
R78 "RC0201FR-07147RL" 0201 3872.4,1734.61 r90 top locked value=147
R79 "RC0201FR-0784R5L" 0201 1209.03,325.59 r0 top locked value=84.5
R80 "RC0201FR-0784R5L" 0201 3772.4,2310.59 r90 top locked value=84.5
R81 "RC0201FR-07147RL" 0201 1209.03,227.6 r0 top locked value=147
R82 "RC0201FR-07147RL" 0201 3872.4,2310.59 r90 top locked value=147
R83 "RC0201FR-0747R5L" 0201 1196.04,277.6 r270 top locked value=47.5
R84 "RC0201FR-0747R5L" 0201 3822.4,2297.6 r0 top locked value=47.5
R85 "RC0201FR-0784R5L" 0201 1730.51,326.89 r180 top locked value=84.5
R86 "RC0201FR-0784R5L" 0201 3772.4,2834.61 r270 top locked value=84.5
R87 "RC0201FR-0747R5L" 0201 1743.5,277.6 r270 top locked value=47.5
R88 "RC0201FR-0747R5L" 0201 3822.4,2847.6 r0 top locked value=47.5
R89 "RC0201FR-07147RL" 0201 1730.51,227.6 r0 top locked value=147
R90 "RC0201FR-07147RL" 0201 3872.4,2834.61 r90 top locked value=147
R91 "RC0201FR-0784R5L" 0201 2306.5,327.59 r0 top locked value=84.5
R92 "RC0201FR-0784R5L" 0201 3772.4,3410.59 r90 top locked value=84.5
R93 "RC0201FR-07147RL" 0201 2306.5,227.6 r0 top locked value=147
R94 "RC0201FR-07147RL" 0201 3872.4,3410.59 r90 top locked value=147
R95 "RC0201FR-0747R5L" 0201 2293.5,277.6 r270 top locked value=47.5
R96 "RC0201FR-0747R5L" 0201 3822.4,3397.6 r0 top locked value=47.5
R97 "RC0201FR-0784R5L" 0201 2833.05,322.6 r180 top locked value=84.5
R98 "RC0201FR-0784R5L" 0201 3430.59,3772.9 r0 top locked value=84.5
R99 "RC0201FR-0747R5L" 0201 2846.04,277.6 r270 top locked value=47.5
R100 "RC0201FR-0747R5L" 0201 3417.6,3822.4 r90 top locked value=47.5
R101 "RC0201FR-07147RL" 0201 2833.05,227.6 r0 top locked value=147
R102 "RC0201FR-07147RL" 0201 3430.59,3872.4 r180 top locked value=147
R103 "RC0201FR-0784R5L" 0201 3409.03,322.6 r0 top locked value=84.5
R104 "RC0201FR-07147RL" 0201 3409.03,227.6 r0 top locked value=147
R105 "RC0201FR-0784R5L" 0201 2854.61,3772.9 r180 top locked value=84.5
R106 "RC0201FR-07147RL" 0201 2854.61,3872.4 r180 top locked value=147
R107 "RC0201FR-0747R5L" 0201 3396.04,277.6 r270 top locked value=47.5
R108 "RC0201FR-0747R5L" 0201 2867.6,3823.82 r90 top locked value=47.5
R109 "RC0201FR-0784R5L" 0201 3772.4,634.61 r270 top locked value=84.5
R110 "RC0201FR-0784R5L" 0201 2330.59,3772.9 r0 top locked value=84.5
R111 "RC0201FR-0747R5L" 0201 3822.4,647.6 r0 top locked value=47.5
R112 "RC0201FR-0747R5L" 0201 2317.6,3822.4 r90 top locked value=47.5
R113 "RC0201FR-07147RL" 0201 3872.4,634.61 r90 top locked value=147
R114 "RC0201FR-07147RL" 0201 2330.59,3872.4 r180 top locked value=147
R115 "RC0201FR-0784R5L" 0201 3772.4,1210.59 r90 top locked value=84.5
R116 "RC0201FR-0784R5L" 0201 1754.61,3772.9 r180 top locked value=84.5
R117 "RC0201FR-07147RL" 0201 3872.4,1210.59 r90 top locked value=147
R118 "RC0201FR-07147RL" 0201 1754.61,3872.4 r180 top locked value=147
R119 "RC0201FR-0747R5L" 0201 3822.4,1197.6 r0 top locked value=47.5
R120 "RC0201FR-0747R5L" 0201 1767.6,3822.4 r90 top locked value=47.5
R121 "MCT06030Z0000ZP500" 0603 1477.6,3667.4 r180 bottom value=0
R122 "MCT06030Z0000ZP500" 0603 1555,3640 r90 top locked value=0
R123 "MCT06030Z0000ZP500" 0603 1776.5,3280 r0 top locked value=0
R124 "CRCW040218K2FKED" 0402 1781.5,3077.61 r270 top locked value=18.2k
R125 "CRCW040249K9FKED" 0402 1841.5,3124.85 r270 top locked value=49.9k
R126 "CRCW0603470RJNEA" 0603 947.4,3502.51 r270 top locked value=470
R127 "CRCW0603470RJNEA" 0603 1397.4,3507.51 r270 top locked value=470
S1 "219-8MST" SW_219-8MST 1060,2440 r90 top locked
S2 "FSM4JSMA" SW_FSM4JSMA 286.78,479.75 r90 top locked
SH1 "SNT-100-BK-G" SNT-100-BK-G 90,2515 r90 top locked value=1x2
SH2 "SNT-100-BK-G" SNT-100-BK-G 1612.6,2782.4 r0 top locked value=1x2
SH3 "SNT-100-BK-G" SNT-100-BK-G 845.35,3421.02 r90 top locked value=1x2
SH4 "SNT-100-BK-G" SNT-100-BK-G 1295.35,3426.02 r90 top locked value=1x2
TP1 "5010" Keystone5010 1725,1490 r0 top locked
TP2 "5010" Keystone5010 1115,3640 r0 top locked
TP3 "5010" Keystone5010 1125,3960 r180 top locked
TP4 "5011" Keystone5011 745,500 r0 top locked
TP5 "5010" Keystone5010 560,3960 r180 top locked
TP6 "5011" Keystone5011 605,3655 r0 top locked
U1 "CDCDB800RSL" RSL0048B-MFG 2050,1790 r0 top locked
U2 "LP5900SD-3.3/NOPB" NGF0006A 435.95,1337.11 r180 top locked
U3 "SN74LVC1G86DBVR" DBV0005A_N 1437.6,932.6 r90 top locked
U4 "TPD4E004DRYR" DRY0006A 391.78,913.29 r180 bottom
U5 "MSP430F5529IPN" PN0080A_N 1267.4,1067.6 r270 bottom
U6 "TPS73533DRBT" DRB0008A 1665,3635 r180 top locked
U7 "TPS74501PDRVR" DRV0006A 1766.5,3187.61 r90 top locked
Y1 "ECS-240-20-5PX-TR" XTAL_CSM-7X 732.4,1047.6 r90 bottom

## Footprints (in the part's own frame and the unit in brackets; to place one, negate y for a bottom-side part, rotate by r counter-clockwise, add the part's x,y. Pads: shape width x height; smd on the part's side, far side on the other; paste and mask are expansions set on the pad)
0201 [mm] "Data from Kemet datasheet CC101_COM dated 7/28/11"
  rect 0.46x0.42 smd mask+0.048: 1(-0.33,0) 2(0.33,0)
  body extent -0.31,-0.16 0.31,0.16, height 0.26
0402 [mm] "0402 from SM-752 data"
  rect 0.8x0.6 smd: 1(-0.6,0) 2(0.6,0)
  silkscreen extent -1.22,-0.52 1.22,0.52, body extent -0.55,-0.3 0.55,0.3, height 0.6
0603 [mm] "0603 from SM-752 data"
  rect 1x0.95 smd: 1(-0.8,0) 2(0.8,0)
  silkscreen extent -1.52,-0.69 1.52,0.69, body extent -0.87,-0.47 0.87,0.47, height 1
0603L [mm] "0603 from SM-752 data"
  rect 0.8x0.85 smd: 1(-0.7,0) 2(0.7,0)
  silkscreen extent -0.07,-0.33 0.07,0.33, body extent -0.87,-0.47 0.87,0.47, height 1
0603S [mil]
  rect 20x35 smd: 1(-30,0) 2(30,0)
  body extent -34,-19 34,19, height 39
0805_HV [mil] "0805 with 30mil clearance between pads"
  rect 50x63 smd: 1(-40,0) 2(40,0)
  silkscreen extent -74,-40 74,40, body extent -43,-29 43,29, height 57
1206 [mm] "1206 from SM-752 data"
  rect 1.3x1.85 smd: 1(-1.45,0) 2(1.45,0)
  silkscreen extent -2.4,-1.21 2.4,1.21, body extent -1.7,-0.9 1.7,0.9, height 1.35
1206_190 [mm] "1206_190"
  rect 1.1x1.6 smd: 1(-1.7,0) 2(1.7,0)
  silkscreen extent -0.9,-1 0.9,1, body extent -1.75,-0.95 1.75,0.95, height 1.9
Bumpon_SJ5003Transparent [mil] "3M Hemispherical Bumpon transparent"
  round 1 on Mech4: 0(0,0)
  silkscreen extent -228,-228 228,228, body extent -219,-219 219,219, height 197
DBV0005A_N [mm] "SOT23, 5-Leads, Body 2.9x1.6mm, Pitch 0.95mm, Lead Span 2.8mm, IPC Medium Density"
  rrect17% 1x0.6 smd: 1(-1.375,0.95) 2(-1.375,0) 3(-1.375,-0.95) 4(1.375,-0.95) 5(1.375,0.95)
  silkscreen extent -1.63,-1.55 0.38,1.55, body extent -1.42,-1.46 1.42,1.46, height 1.09
DRB0008A [mm] "VSON-8"
  rrect32% 0.6x0.31 smd: 1(-1.4,0.975) 2(-1.4,0.325) 3(-1.4,-0.325) 4(-1.4,-0.975) 5(1.4,-0.975) 6(1.4,-0.325) 7(1.4,0.325) 8(1.4,0.975)
  rrect7% 1.5x1.75 smd paste-0.75: 9(0,0)
  Layer 1 - Top Layer region: -0.7,-0.875 -0.49,-0.875 -0.471,-0.879 -0.455,-0.89 -0.444,-0.906 -0.44,-0.925 -0.44,-0.925 -0.44,-1.65 -0.436,-1.669 -0.425,-1.685 -0.409,-1.696 -0.39,-1.7 -0.39,-1.7 -0.26,-1.7 -0.241,-1.696 -0.225,-1.685 -0.214,-1.669 -0.21,-1.65 -0.21,-1.65 -0.21,-0.925 -0.206,-0.906 -0.195,-0.89 -0.179,-0.879 -0.16,-0.875 -0.16,-0.875 0.16,-0.875 0.179,-0.879 0.195,-0.89 0.206,-0.906 0.21,-0.925 0.21,-0.925 0.21,-1.65 0.21,-1.65 0.214,-1.669 0.225,-1.685 0.241,-1.696 0.26,-1.7 0.26,-1.7 0.39,-1.7 0.409,-1.696 0.425,-1.685 0.436,-1.669 0.44,-1.65 0.44,-1.65 0.44,-0.925 0.444,-0.906 0.455,-0.89 0.471,-0.879 0.49,-0.875 0.49,-0.875 0.7,-0.875 0.719,-0.871 0.735,-0.86 0.746,-0.844 0.75,-0.825 0.75,-0.825 0.75,0.825 0.746,0.844 0.735,0.86 0.719,0.871 0.7,0.875 0.7,0.875 0.49,0.875 0.471,0.879 0.455,0.89 0.444,0.906 0.44,0.925 0.44,0.925 0.44,1.65 0.436,1.669 0.425,1.685 0.409,1.696 0.39,1.7 0.39,1.7 0.26,1.7 0.241,1.696 0.225,1.685 0.214,1.669 0.21,1.65 0.21,1.65 0.21,1.65 0.21,0.925 0.206,0.906 0.195,0.89 0.179,0.879 0.16,0.875 0.16,0.875 -0.16,0.875 -0.179,0.879 -0.195,0.89 -0.206,0.906 -0.21,0.925 -0.21,0.925 -0.21,1.65 -0.214,1.669 -0.225,1.685 -0.241,1.696 -0.26,1.7 -0.26,1.7 -0.39,1.7 -0.409,1.696 -0.425,1.685 -0.436,1.669 -0.44,1.65 -0.44,1.65 -0.44,0.925 -0.444,0.906 -0.455,0.89 -0.471,0.879 -0.49,0.875 -0.49,0.875 -0.7,0.875 -0.719,0.871 -0.735,0.86 -0.746,0.844 -0.75,0.825 -0.75,0.825 -0.75,-0.825 -0.746,-0.844 -0.735,-0.86 -0.719,-0.871 -0.7,-0.875
  silkscreen extent -1.73,-1.73 1.73,1.73, body extent -1.5,-1.5 1.5,1.5, height 0.77
DRV0006A [mm] "SON, 6-Leads, Body 2x2mm, Pitch 0.65mm, Thermal Pad 1.6x1mm, TI Recommended"
  rrect33% 0.45x0.3 smd: 1(-0.975,0.65) 2(-0.975,0) 3(-0.975,-0.65) 4(0.975,-0.65) 5(0.975,0) 6(0.975,0.65)
  rrect14% 1x0.7 on Top Paste: 7(0,0.45) 7(0,-0.45)
  rrect10% 1x1.6 smd paste-0.5: 7(0,0)
  silkscreen extent -1.05,-1.2 1.05,1.2, body extent -1.05,-1.05 1.05,1.05, height 0.81
DRY0006A [mm] "USON-6"
  rrect67% 0.45x0.3 smd paste-0.05 mask-0.05: 1(-0.275,0.5)
  rrect67% 0.4x0.3 smd paste-0.05 mask-0.05: 2(-0.3,0) 3(-0.3,-0.5) 4(0.3,-0.5) 5(0.3,0) 6(0.3,0.5)
  body extent -0.5,-0.72 0.5,0.72, height 0.58
FCI_10118194-0001LF [mm] "USB-micro B USB 2.0, 0.65mm, 5 Pos, R/A, SMT"
  rrect25% 0.4x1.35 smd: 1(-1.3,4.125) 2(-0.65,4.125) 3(0,4.125) 4(0.65,4.125) 5(1.3,4.125)
  rrect100% 1.25x0.95 hole 0.55 slot 0.85 at 0 deg mask+0.064: 6(-2.5,4.15) 7(2.5,4.15)
  rrect50% 1.008x1.55 hole 0.5 slot 1.15 at 90 deg: 8(-3.5,1.45) 9(3.5,1.45)
  rrect7% 1.5x1.55 smd: 10(-1,1.45) 11(1,1.45)
  Layer 1 - Top Layer region: -3.445,0.675 -3.544,0.675 -3.728,0.751 -3.869,0.892 -3.945,1.076 -3.945,1.175 -3.945,1.175 -3.945,1.175 -3.945,1.725 -3.945,1.824 -3.869,2.008 -3.728,2.149 -3.544,2.225 -3.445,2.225 -3.445,2.225 -2.3,2.225 -2.3,0.675
  Layer 1 - Top Layer region: 3.445,0.675 3.544,0.675 3.728,0.751 3.869,0.892 3.945,1.076 3.945,1.175 3.945,1.175 3.945,1.175 3.945,1.725 3.945,1.824 3.869,2.008 3.728,2.149 3.544,2.225 3.445,2.225 3.445,2.225 2.3,2.225 2.3,0.675
  silkscreen extent -4,2.6 3.7,4.3, body extent -4.02,-1.23 4.03,4.35, height 2.72
Fiducial10-20 [mm]
  round 1 smd mask+0.5: 1(0,0)
  Layer 1 - Top Layer keep-out circle w1.178: c0,0 r0.5
FP-SMA-EDGE-S-CUSTOM [mm]
  rrect21% 0.483x5 smd paste+0 mask+0: 1(0,-7.26)
  rrect6% 1.6x5 smd paste+0 mask+0: 2(-2.77,-7.26) 3(2.77,-7.26)
  rrect6% 1.6x5 smd far side paste+0 mask+0: 4(-2.77,-7.26) 5(2.77,-7.26)
  silkscreen extent -3.18,-10.59 3.17,4.76, body extent -3.87,-10.05 3.87,5.05, height 0.25
Keystone5010 [mil] "Keystone Multipurpose loops"
  round 87 hole 63: 1(0,0)
  silkscreen extent -70,-70 70,70, body extent -63,-63 63,62, height 319
Keystone5011 [mil] "Keystone Multipurpose loops"
  round 87 hole 63: 1(0,0)
  silkscreen extent -70,-70 70,70, body extent -63,-63 63,62, height 319
LED_LTST-C170_Red [mm] "LITE-ON"
  rect 1.2x1.2 smd: 1(-1.05,0) 2(1.05,0)
  silkscreen extent -1.6,-1 2.2,1, body extent -1.05,-0.67 1.05,0.67, height 1.1
LED_LTST-C190 [mm] "Lite-On"
  rect 0.8x0.8 smd: 1(-0.75,0) 2(0.75,0)
  silkscreen extent -1.1,-0.8 1.8,0.8, body extent -0.85,-0.45 0.85,0.45, height 0.9
NGF0006A [mm] "TI"
  rect 0.6x0.25 smd: 1(-1.15,0.65) 2(-1.15,0) 3(-1.15,-0.65) 4(1.15,-0.65) 5(1.15,0) 6(1.15,0.65)
  rect 0.75x1.2 smd paste-0.38: 7(0,0)
  silkscreen extent -1.4,-1.25 1.4,1.25, body extent -1.3,-1.15 1.3,1.15, height 0.81
PN0080A_N [mm] "QFP, 80-Leads, Body 12x12mm, Pitch 0.5mm, IPC Medium Density"
  oval 1.45x0.3 smd: 1(-6.725,4.75) 2(-6.725,4.25) 3(-6.725,3.75) 4(-6.725,3.25) 5(-6.725,2.75) 6(-6.725,2.25) 7(-6.725,1.75) 8(-6.725,1.25) 9(-6.725,0.75) 10(-6.725,0.25) 11(-6.725,-0.25) 12(-6.725,-0.75) 13(-6.725,-1.25) 14(-6.725,-1.75) 15(-6.725,-2.25) 16(-6.725,-2.75) 17(-6.725,-3.25) 18(-6.725,-3.75) 19(-6.725,-4.25) 20(-6.725,-4.75) 41(6.725,-4.75) 42(6.725,-4.25) 43(6.725,-3.75) 44(6.725,-3.25) 45(6.725,-2.75) 46(6.725,-2.25) 47(6.725,-1.75) 48(6.725,-1.25) 49(6.725,-0.75) 50(6.725,-0.25) 51(6.725,0.25) 52(6.725,0.75) 53(6.725,1.25) 54(6.725,1.75) 55(6.725,2.25) 56(6.725,2.75) 57(6.725,3.25) 58(6.725,3.75) 59(6.725,4.25) 60(6.725,4.75)
  oval 0.3x1.45 smd: 21(-4.75,-6.725) 22(-4.25,-6.725) 23(-3.75,-6.725) 24(-3.25,-6.725) 25(-2.75,-6.725) 26(-2.25,-6.725) 27(-1.75,-6.725) 28(-1.25,-6.725) 29(-0.75,-6.725) 30(-0.25,-6.725) 31(0.25,-6.725) 32(0.75,-6.725) 33(1.25,-6.725) 34(1.75,-6.725) 35(2.25,-6.725) 36(2.75,-6.725) 37(3.25,-6.725) 38(3.75,-6.725) 39(4.25,-6.725) 40(4.75,-6.725) 61(4.75,6.725) 62(4.25,6.725) 63(3.75,6.725) 64(3.25,6.725) 65(2.75,6.725) 66(2.25,6.725) 67(1.75,6.725) 68(1.25,6.725) 69(0.75,6.725) 70(0.25,6.725) 71(-0.25,6.725) 72(-0.75,6.725) 73(-1.25,6.725) 74(-1.75,6.725) 75(-2.25,6.725) 76(-2.75,6.725) 77(-3.25,6.725) 78(-3.75,6.725) 79(-4.25,6.725) 80(-4.75,6.725)
  silkscreen extent -6.85,-5.6 5.6,5.6, body extent -7,-7 7,7, height 1.56
RSL0048B-MFG [mm]
  round 0.18 smd paste-1000 mask+0: 1(-2.975,2.2) 2(-2.975,1.8) 3(-2.975,1.4) 4(-2.975,1) 5(-2.985,0.6) 6(-2.975,0.2) 7(-2.975,-0.2) 8(-2.975,-0.6) 9(-2.975,-1) 10(-2.975,-1.4) 11(-2.975,-1.8) 12(-3.3,-2.2) 13(-2.2,-2.975) 14(-1.8,-2.975) 15(-1.4,-2.975) 16(-1,-2.975) 17(-0.6,-2.985) 18(-0.2,-2.975) 19(0.2,-2.975) 20(0.6,-2.975) 21(1,-2.975) 22(1.4,-2.975) 23(1.8,-2.975) 24(2.2,-3.3) 25(2.975,-2.2) 26(2.975,-1.8) 27(2.975,-1.4) 28(2.975,-1) 29(2.985,-0.6) 30(2.975,-0.2) 31(2.975,0.2) 32(2.975,0.6) 33(2.975,1) 34(2.975,1.4) 35(2.975,1.8) 36(3.25,2.2) 37(2.2,2.975) 38(1.8,2.975) 39(1.4,2.975) 40(1,2.975) 41(0.6,2.985) 42(0.2,2.975) 43(-0.2,2.975) 44(-0.6,2.975) 45(-1,2.975) 46(-1.4,2.975) 47(-1.8,2.975) 48(-2.2,3.25)
  rrect2% 4.4x4.4 smd paste-1000 mask+0: 49(0,0)
  Layer 1 - Top Layer region: -3.4,2.3 -2.65,2.3 -2.612,2.292 -2.579,2.271 -2.558,2.238 -2.55,2.2 -2.55,2.2 -2.563,2.15 -2.6,2.113 -2.65,2.1 -2.65,2.1 -3.4,2.1
  Layer 1 - Top Layer region: -3.4,1.9 -2.65,1.9 -2.612,1.892 -2.579,1.871 -2.558,1.838 -2.55,1.8 -2.55,1.8 -2.563,1.75 -2.6,1.713 -2.65,1.7 -2.65,1.7 -3.4,1.7
  Layer 1 - Top Layer region: -3.4,1.5 -2.65,1.5 -2.612,1.492 -2.579,1.471 -2.558,1.438 -2.55,1.4 -2.55,1.4 -2.563,1.35 -2.6,1.313 -2.65,1.3 -2.65,1.3 -3.4,1.3
  Layer 1 - Top Layer region: -3.4,1.1 -2.65,1.1 -2.612,1.092 -2.579,1.071 -2.558,1.038 -2.55,1 -2.55,1 -2.563,0.95 -2.6,0.913 -2.65,0.9 -2.65,0.9 -3.4,0.9
  Layer 1 - Top Layer region: -3.4,0.7 -2.65,0.7 -2.612,0.692 -2.579,0.671 -2.558,0.638 -2.55,0.6 -2.55,0.6 -2.563,0.55 -2.6,0.513 -2.65,0.5 -2.65,0.5 -3.4,0.5
  Layer 1 - Top Layer region: -3.4,0.3 -2.65,0.3 -2.612,0.292 -2.579,0.271 -2.558,0.238 -2.55,0.2 -2.55,0.2 -2.563,0.15 -2.6,0.113 -2.65,0.1 -2.65,0.1 -3.4,0.1
  Layer 1 - Top Layer region: -3.4,-0.1 -2.65,-0.1 -2.612,-0.108 -2.579,-0.129 -2.558,-0.162 -2.55,-0.2 -2.55,-0.2 -2.563,-0.25 -2.6,-0.287 -2.65,-0.3 -2.65,-0.3 -3.4,-0.3
  Layer 1 - Top Layer region: -3.4,-0.5 -2.65,-0.5 -2.612,-0.508 -2.579,-0.529 -2.558,-0.562 -2.55,-0.6 -2.55,-0.6 -2.563,-0.65 -2.6,-0.687 -2.65,-0.7 -2.65,-0.7 -3.4,-0.7
  Layer 1 - Top Layer region: -3.4,-0.9 -2.65,-0.9 -2.612,-0.908 -2.579,-0.929 -2.558,-0.962 -2.55,-1 -2.55,-1 -2.558,-1.038 -2.579,-1.071 -2.612,-1.092 -2.65,-1.1 -2.65,-1.1 -3.4,-1.1
  Layer 1 - Top Layer region: -3.4,-1.3 -2.65,-1.3 -2.612,-1.308 -2.579,-1.329 -2.558,-1.362 -2.55,-1.4 -2.55,-1.4 -2.563,-1.45 -2.6,-1.487 -2.65,-1.5 -2.65,-1.5 -3.4,-1.5
  Layer 1 - Top Layer region: -3.4,-1.7 -2.65,-1.7 -2.612,-1.708 -2.579,-1.729 -2.558,-1.762 -2.55,-1.8 -2.55,-1.8 -2.563,-1.85 -2.6,-1.887 -2.65,-1.9 -2.65,-1.9 -3.4,-1.9
  Layer 1 - Top Layer region: -3.4,-2.1 -2.65,-2.1 -2.612,-2.108 -2.579,-2.129 -2.558,-2.162 -2.55,-2.2 -2.55,-2.2 -2.563,-2.25 -2.6,-2.287 -2.65,-2.3 -2.65,-2.3 -3.4,-2.3
  Layer 1 - Top Layer region: 3.4,-2.3 2.65,-2.3 2.612,-2.292 2.579,-2.271 2.558,-2.238 2.55,-2.2 2.55,-2.2 2.558,-2.162 2.579,-2.129 2.612,-2.108 2.65,-2.1 2.65,-2.1 3.4,-2.1
  Layer 1 - Top Layer region: 3.4,-1.9 2.65,-1.9 2.612,-1.892 2.579,-1.871 2.558,-1.838 2.55,-1.8 2.55,-1.8 2.558,-1.762 2.579,-1.729 2.612,-1.708 2.65,-1.7 2.65,-1.7 3.4,-1.7
  Layer 1 - Top Layer region: 3.4,-1.5 2.65,-1.5 2.612,-1.492 2.579,-1.471 2.558,-1.438 2.55,-1.4 2.55,-1.4 2.558,-1.362 2.579,-1.329 2.612,-1.308 2.65,-1.3 2.65,-1.3 3.4,-1.3
  Layer 1 - Top Layer region: 3.4,-1.1 2.65,-1.1 2.612,-1.092 2.579,-1.071 2.558,-1.038 2.55,-1 2.55,-1 2.558,-0.962 2.579,-0.929 2.612,-0.908 2.65,-0.9 2.65,-0.9 3.4,-0.9
  Layer 1 - Top Layer region: 3.4,-0.7 2.65,-0.7 2.612,-0.692 2.579,-0.671 2.558,-0.638 2.55,-0.6 2.55,-0.6 2.558,-0.562 2.579,-0.529 2.612,-0.508 2.65,-0.5 2.65,-0.5 3.4,-0.5
  Layer 1 - Top Layer region: 3.4,-0.3 2.65,-0.3 2.612,-0.292 2.579,-0.271 2.558,-0.238 2.55,-0.2 2.55,-0.2 2.558,-0.162 2.579,-0.129 2.612,-0.108 2.65,-0.1 2.65,-0.1 3.4,-0.1
  Layer 1 - Top Layer region: 3.4,0.1 2.65,0.1 2.612,0.108 2.579,0.129 2.558,0.162 2.55,0.2 2.55,0.2 2.558,0.238 2.579,0.271 2.612,0.292 2.65,0.3 2.65,0.3 3.4,0.3
  Layer 1 - Top Layer region: 3.4,0.5 2.65,0.5 2.612,0.508 2.579,0.529 2.558,0.562 2.55,0.6 2.55,0.6 2.558,0.638 2.579,0.671 2.612,0.692 2.65,0.7 2.65,0.7 3.4,0.7
  Layer 1 - Top Layer region: 3.4,0.9 2.65,0.9 2.612,0.908 2.579,0.929 2.558,0.962 2.55,1 2.55,1 2.558,1.038 2.579,1.071 2.612,1.092 2.65,1.1 2.65,1.1 3.4,1.1
  Layer 1 - Top Layer region: 3.4,1.3 2.65,1.3 2.612,1.308 2.579,1.329 2.558,1.362 2.55,1.4 2.55,1.4 2.558,1.438 2.579,1.471 2.612,1.492 2.65,1.5 2.65,1.5 3.4,1.5
  Layer 1 - Top Layer region: 3.4,1.7 2.65,1.7 2.612,1.708 2.579,1.729 2.558,1.762 2.55,1.8 2.55,1.8 2.558,1.838 2.579,1.871 2.612,1.892 2.65,1.9 2.65,1.9 3.4,1.9
  Layer 1 - Top Layer region: 3.4,2.1 2.65,2.1 2.612,2.108 2.579,2.129 2.558,2.162 2.55,2.2 2.55,2.2 2.558,2.238 2.579,2.271 2.612,2.292 2.65,2.3 2.65,2.3 3.4,2.3
  Layer 1 - Top Layer region: -2.3,-3.4 -2.3,-2.65 -2.292,-2.612 -2.271,-2.579 -2.238,-2.558 -2.2,-2.55 -2.2,-2.55 -2.162,-2.558 -2.129,-2.579 -2.108,-2.612 -2.1,-2.65 -2.1,-2.65 -2.1,-3.4
  Layer 1 - Top Layer region: -1.9,-3.4 -1.9,-2.65 -1.892,-2.612 -1.871,-2.579 -1.838,-2.558 -1.8,-2.55 -1.8,-2.55 -1.762,-2.558 -1.729,-2.579 -1.708,-2.612 -1.7,-2.65 -1.7,-2.65 -1.7,-3.4
  Layer 1 - Top Layer region: -1.5,-3.4 -1.5,-2.65 -1.492,-2.612 -1.471,-2.579 -1.438,-2.558 -1.4,-2.55 -1.4,-2.55 -1.362,-2.558 -1.329,-2.579 -1.308,-2.612 -1.3,-2.65 -1.3,-2.65 -1.3,-3.4
  Layer 1 - Top Layer region: -1.1,-3.4 -1.1,-2.65 -1.092,-2.612 -1.071,-2.579 -1.038,-2.558 -1,-2.55 -1,-2.55 -0.962,-2.558 -0.929,-2.579 -0.908,-2.612 -0.9,-2.65 -0.9,-2.65 -0.9,-3.4
  Layer 1 - Top Layer region: -0.7,-3.4 -0.7,-2.65 -0.692,-2.612 -0.671,-2.579 -0.638,-2.558 -0.6,-2.55 -0.6,-2.55 -0.562,-2.558 -0.529,-2.579 -0.508,-2.612 -0.5,-2.65 -0.5,-2.65 -0.5,-3.4
  Layer 1 - Top Layer region: -0.3,-3.4 -0.3,-2.65 -0.292,-2.612 -0.271,-2.579 -0.238,-2.558 -0.2,-2.55 -0.2,-2.55 -0.162,-2.558 -0.129,-2.579 -0.108,-2.612 -0.1,-2.65 -0.1,-2.65 -0.1,-3.4
  Layer 1 - Top Layer region: 0.1,-3.4 0.1,-2.65 0.108,-2.612 0.129,-2.579 0.162,-2.558 0.2,-2.55 0.2,-2.55 0.238,-2.558 0.271,-2.579 0.292,-2.612 0.3,-2.65 0.3,-2.65 0.3,-3.4
  Layer 1 - Top Layer region: 0.5,-3.4 0.5,-2.65 0.508,-2.612 0.529,-2.579 0.562,-2.558 0.6,-2.55 0.6,-2.55 0.638,-2.558 0.671,-2.579 0.692,-2.612 0.7,-2.65 0.7,-2.65 0.7,-3.4
  Layer 1 - Top Layer region: 0.9,-3.4 0.9,-2.65 0.908,-2.612 0.929,-2.579 0.962,-2.558 1,-2.55 1,-2.55 1.038,-2.558 1.071,-2.579 1.092,-2.612 1.1,-2.65 1.1,-2.65 1.1,-3.4
  Layer 1 - Top Layer region: 1.3,-3.4 1.3,-2.65 1.308,-2.612 1.329,-2.579 1.362,-2.558 1.4,-2.55 1.4,-2.55 1.438,-2.558 1.471,-2.579 1.492,-2.612 1.5,-2.65 1.5,-2.65 1.5,-3.4
  Layer 1 - Top Layer region: 1.7,-3.4 1.7,-2.65 1.708,-2.612 1.729,-2.579 1.762,-2.558 1.8,-2.55 1.8,-2.55 1.838,-2.558 1.871,-2.579 1.892,-2.612 1.9,-2.65 1.9,-2.65 1.9,-3.4
  Layer 1 - Top Layer region: 2.1,-3.4 2.1,-2.65 2.108,-2.612 2.129,-2.579 2.162,-2.558 2.2,-2.55 2.2,-2.55 2.238,-2.558 2.271,-2.579 2.292,-2.612 2.3,-2.65 2.3,-2.65 2.3,-3.4
  Layer 1 - Top Layer region: 2.3,3.4 2.3,2.65 2.287,2.6 2.25,2.563 2.2,2.55 2.2,2.55 2.162,2.558 2.129,2.579 2.108,2.612 2.1,2.65 2.1,2.65 2.1,3.4
  Layer 1 - Top Layer region: 1.9,3.4 1.9,2.65 1.887,2.6 1.85,2.563 1.8,2.55 1.8,2.55 1.762,2.558 1.729,2.579 1.708,2.612 1.7,2.65 1.7,2.65 1.7,3.4
  Layer 1 - Top Layer region: 1.5,3.4 1.5,2.65 1.487,2.6 1.45,2.563 1.4,2.55 1.4,2.55 1.362,2.558 1.329,2.579 1.308,2.612 1.3,2.65 1.3,2.65 1.3,3.4
  Layer 1 - Top Layer region: 1.1,3.4 1.1,2.65 1.092,2.612 1.071,2.579 1.038,2.558 1,2.55 1,2.55 0.962,2.558 0.929,2.579 0.908,2.612 0.9,2.65 0.9,2.65 0.9,3.4
  Layer 1 - Top Layer region: 0.7,3.4 0.7,2.65 0.687,2.6 0.65,2.563 0.6,2.55 0.6,2.55 0.562,2.558 0.529,2.579 0.508,2.612 0.5,2.65 0.5,2.65 0.5,3.4
  Layer 1 - Top Layer region: 0.3,3.4 0.3,2.65 0.287,2.6 0.25,2.563 0.2,2.55 0.2,2.55 0.162,2.558 0.129,2.579 0.108,2.612 0.1,2.65 0.1,2.65 0.1,3.4
  Layer 1 - Top Layer region: -0.1,3.4 -0.1,2.65 -0.113,2.6 -0.15,2.563 -0.2,2.55 -0.2,2.55 -0.238,2.558 -0.271,2.579 -0.292,2.612 -0.3,2.65 -0.3,2.65 -0.3,3.4
  Layer 1 - Top Layer region: -0.5,3.4 -0.5,2.65 -0.513,2.6 -0.55,2.563 -0.6,2.55 -0.6,2.55 -0.638,2.558 -0.671,2.579 -0.692,2.612 -0.7,2.65 -0.7,2.65 -0.7,3.4
  Layer 1 - Top Layer region: -0.9,3.4 -0.9,2.65 -0.908,2.612 -0.929,2.579 -0.962,2.558 -1,2.55 -1,2.55 -1.038,2.558 -1.071,2.579 -1.092,2.612 -1.1,2.65 -1.1,2.65 -1.1,3.4
  Layer 1 - Top Layer region: -1.3,3.4 -1.3,2.65 -1.313,2.6 -1.35,2.563 -1.4,2.55 -1.4,2.55 -1.438,2.558 -1.471,2.579 -1.492,2.612 -1.5,2.65 -1.5,2.65 -1.5,3.4
  Layer 1 - Top Layer region: -1.7,3.4 -1.7,2.65 -1.708,2.612 -1.729,2.579 -1.762,2.558 -1.8,2.55 -1.8,2.55 -1.838,2.558 -1.871,2.579 -1.892,2.612 -1.9,2.65 -1.9,2.65 -1.9,3.4
  Layer 1 - Top Layer region: -2.1,3.4 -2.1,2.65 -2.113,2.6 -2.15,2.563 -2.2,2.55 -2.2,2.55 -2.238,2.558 -2.271,2.579 -2.292,2.612 -2.3,2.65 -2.3,2.65 -2.3,3.4
  silkscreen extent -4.1,-3.08 3.08,3.08, body extent -3.5,-3.5 3.5,3.5, height 0.25
SAMTEC_MTSW-115-22-G-D-315 [mm] "Samtec"
  rect 1.65x1.65 hole 1.016: 1(-17.78,-1.27)
  round 1.65 hole 1.016: 2(-17.78,1.27) 3(-15.24,-1.27) 4(-15.24,1.27) 5(-12.7,-1.27) 6(-12.7,1.27) 7(-10.16,-1.27) 8(-10.16,1.27) 9(-7.62,-1.27) 10(-7.62,1.27) 11(-5.08,-1.27) 12(-5.08,1.27) 13(-2.54,-1.27) 14(-2.54,1.27) 15(0,-1.27) 16(0,1.27) 17(2.54,-1.27) 18(2.54,1.27) 19(5.08,-1.27) 20(5.08,1.27) 21(7.62,-1.27) 22(7.62,1.27) 23(10.16,-1.27) 24(10.16,1.27) 25(12.7,-1.27) 26(12.7,1.27) 27(15.24,-1.27) 28(15.24,1.27) 29(17.78,-1.27) 30(17.78,1.27)
  silkscreen extent -19.14,-3.05 19.05,2.54, body extent -19.05,-2.54 19.05,2.54, height 10.54
SMB [mil] "Molded Diode, 2-Leads, Body 5.4x3.6mm, IPC Medium Density, based on OnSemi component dimensions"
  rect 85x107.99 smd: 1(-87.01,0) 2(87.01,0)
  silkscreen extent -155,-82 125,82, body extent -106,-71 106,71, height 91
SNT-100-BK-G [mil] "Samtec STEP model"
  round 1 on Mech3: 0(0,0)
  body extent -100,-50 100,50, height 344
SOT-23 [mm] "SOT23, 3-Leads, Body 2.9x1.3mm, Pitch 0.95mm, Lead Span 2.5mm, IPC Medium Density"
  rrect50% 1x0.6 smd: 1(-1.2,0.95) 2(-1.2,-0.95) 3(1.2,0)
  silkscreen extent -1.63,-1.5 0.7,1.5, body extent -1.16,-1.45 1.21,1.45, height 1
SW_219-8MST [mm] "SW, Tape Seal, 8POS, SMD"
  rect 2.44x1.12 smd: 1(-4.3,8.89) 2(-4.3,6.35) 3(-4.3,3.81) 4(-4.3,1.27) 5(-4.3,-1.27) 6(-4.3,-3.81) 7(-4.3,-6.35) 8(-4.3,-8.89) 9(4.3,-8.89) 10(4.3,-6.35) 11(4.3,-3.81) 12(4.3,-1.27) 13(4.3,1.27) 14(4.3,3.81) 15(4.3,6.35) 16(4.3,8.89)
  silkscreen extent -5.45,-10.92 2.54,10.89, body extent -4.95,-10.89 4.95,10.9, height 4.32
SW_FSM4JSMA [mm] "Alcoswitch"
  rrect7% 1.4x2.1 smd: 1(2.25,4.55) 2(2.25,-4.55) 3(-2.25,4.55) 4(-2.25,-4.55)
  body extent -3,-5 3,5, height 5.09
TEC_282834-2 [mm] "TEC"
  rect 1.6x1.6 hole 1.1: 1(-1.27,0)
  round 1.6 hole 1.1: 2(1.27,0)
  silkscreen extent -3.66,-3.4 2.9,3.4, body extent -2.77,-3.25 2.77,3.25, height 10.01
TSW-103-07-G-S [mm] "Samtec 100mil, 1x3, 230 mil above insulator"
  rrect50% 1.65x1.65 hole 1.016: 1(-2.54,0)
  round 1.65 hole 1.016: 2(0,0) 3(2.54,0)
  body extent -3.81,-1.27 3.81,1.27, height 8.38
XTAL_CSM-7X [mm] "ECS"
  rect 5.5x2 smd: 1(-4.75,0) 2(4.75,0)
  silkscreen extent -6.2,-2.5 6.2,2.5, body extent -5.95,-2.4 5.95,2.4, height 4.3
